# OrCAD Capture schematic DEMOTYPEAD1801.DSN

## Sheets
1 09 PCIA_USER_S: size A3
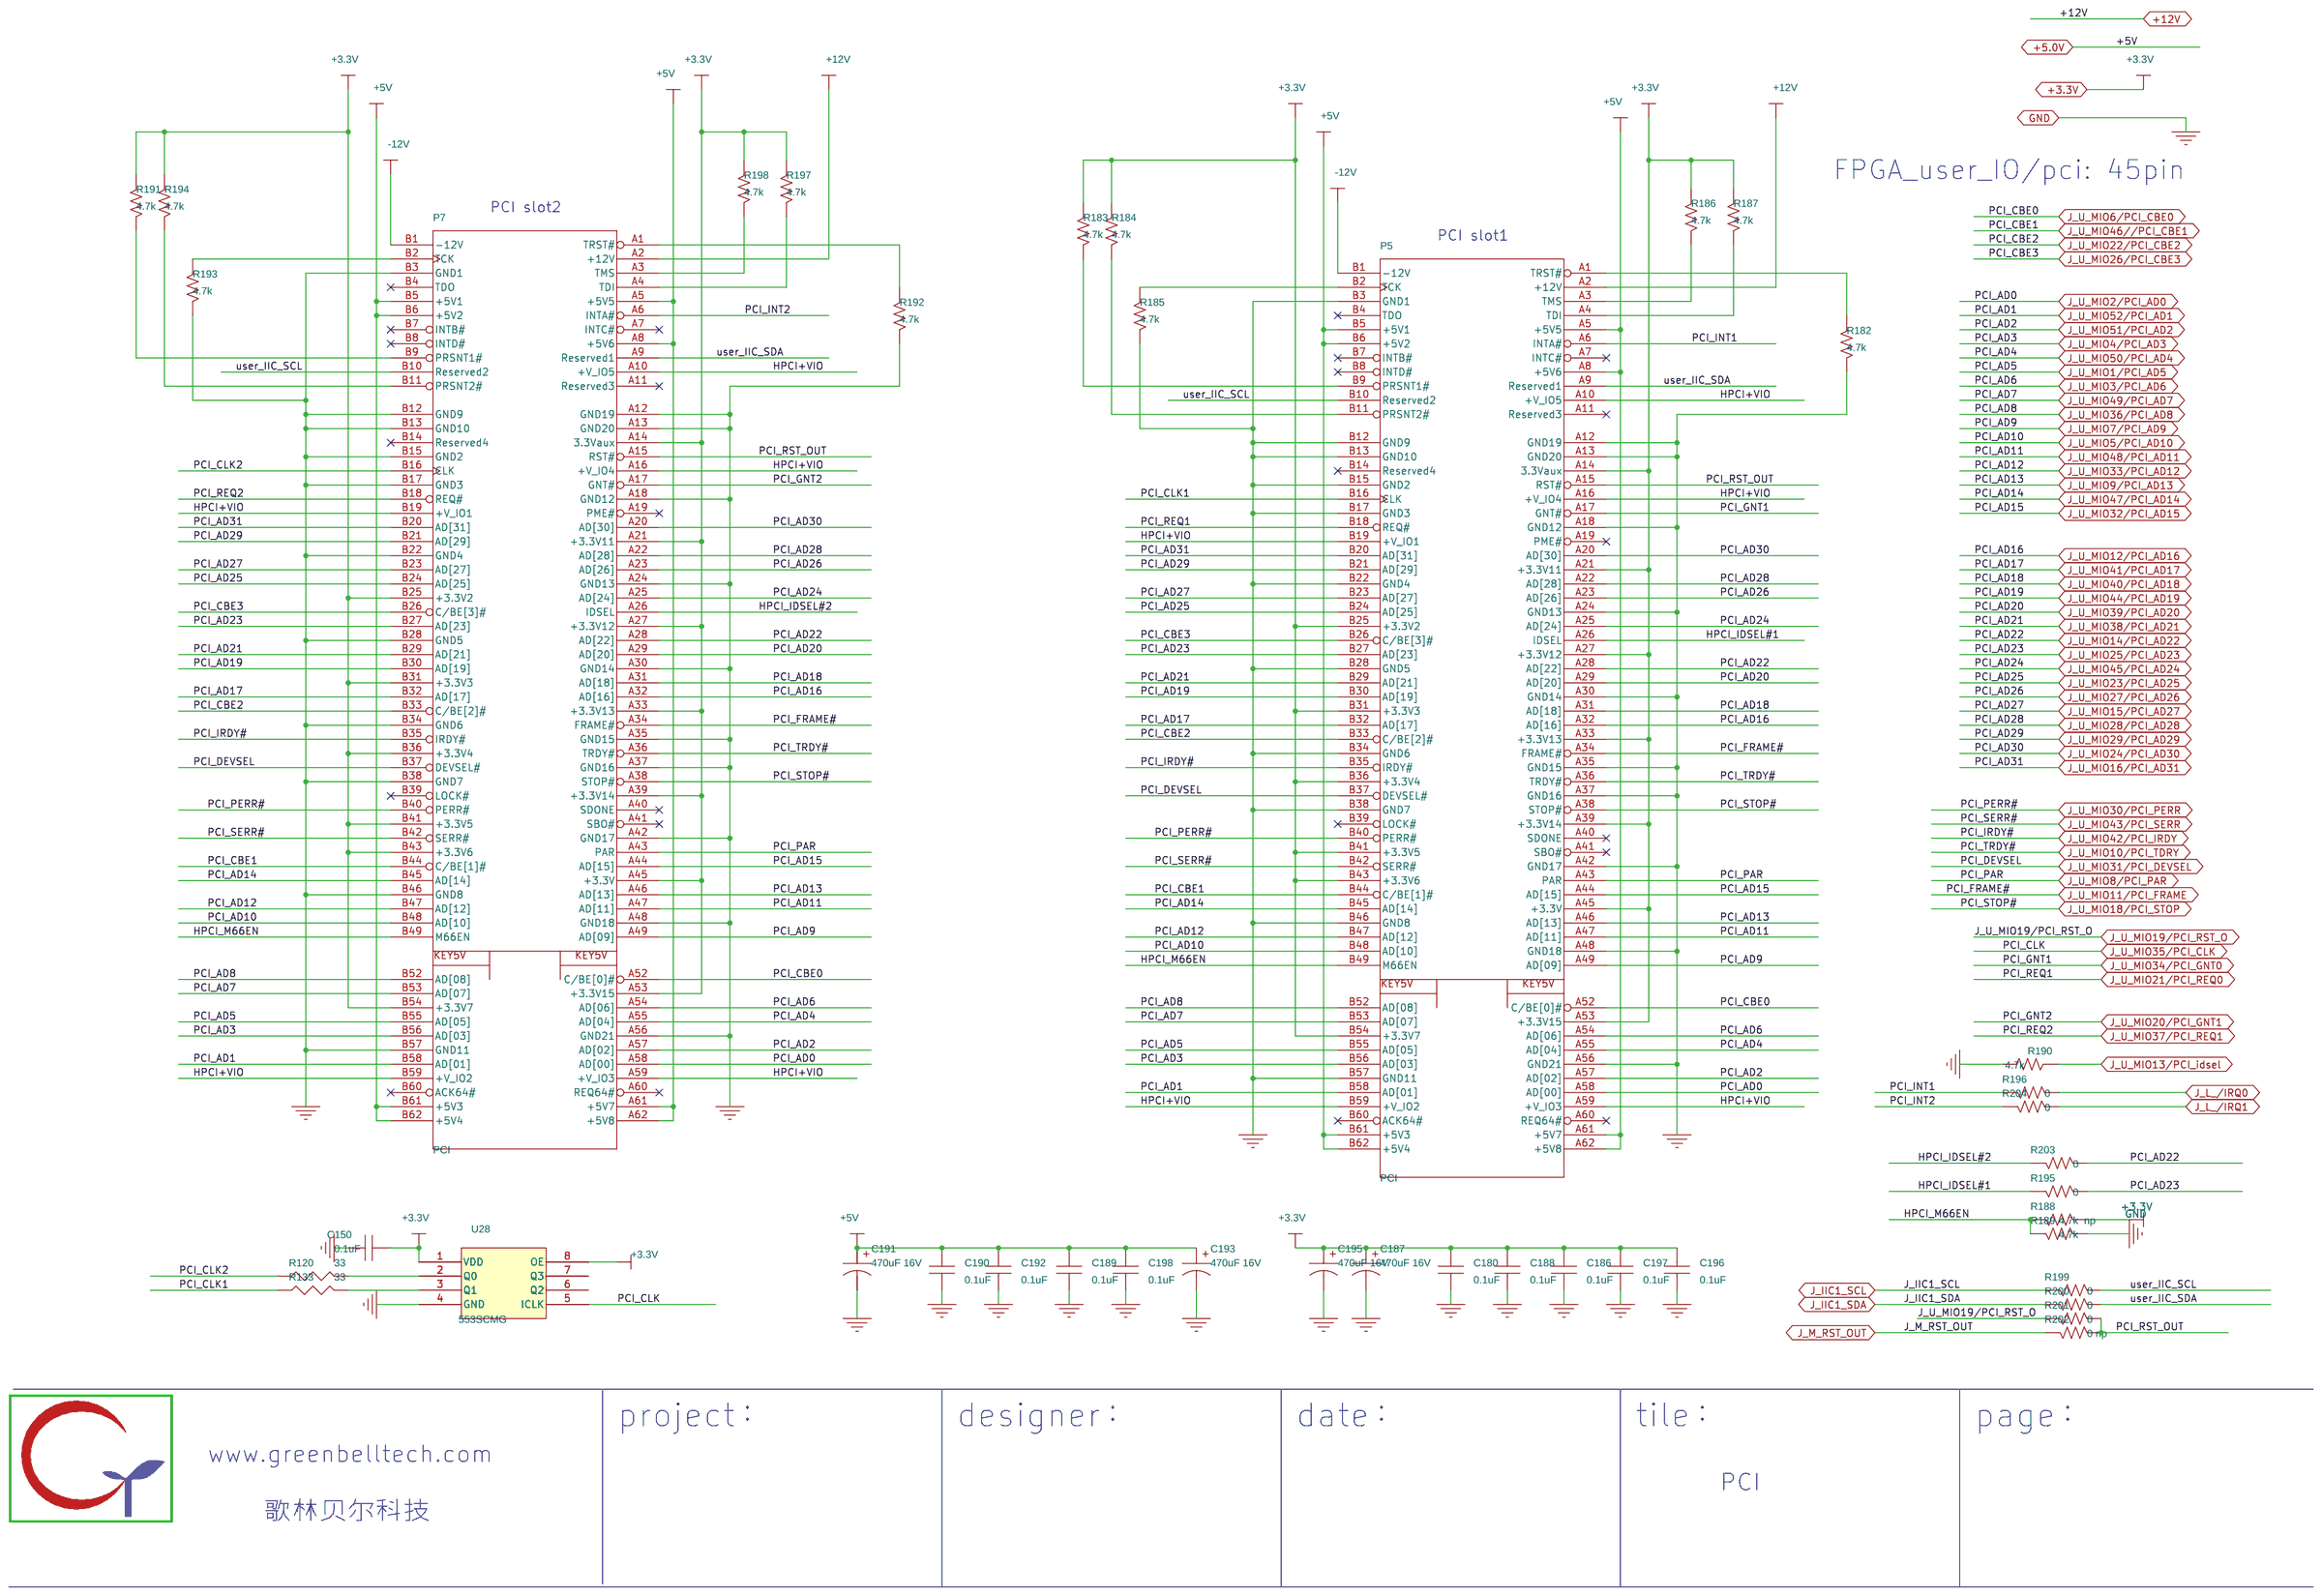
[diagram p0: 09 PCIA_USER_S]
2 00 index
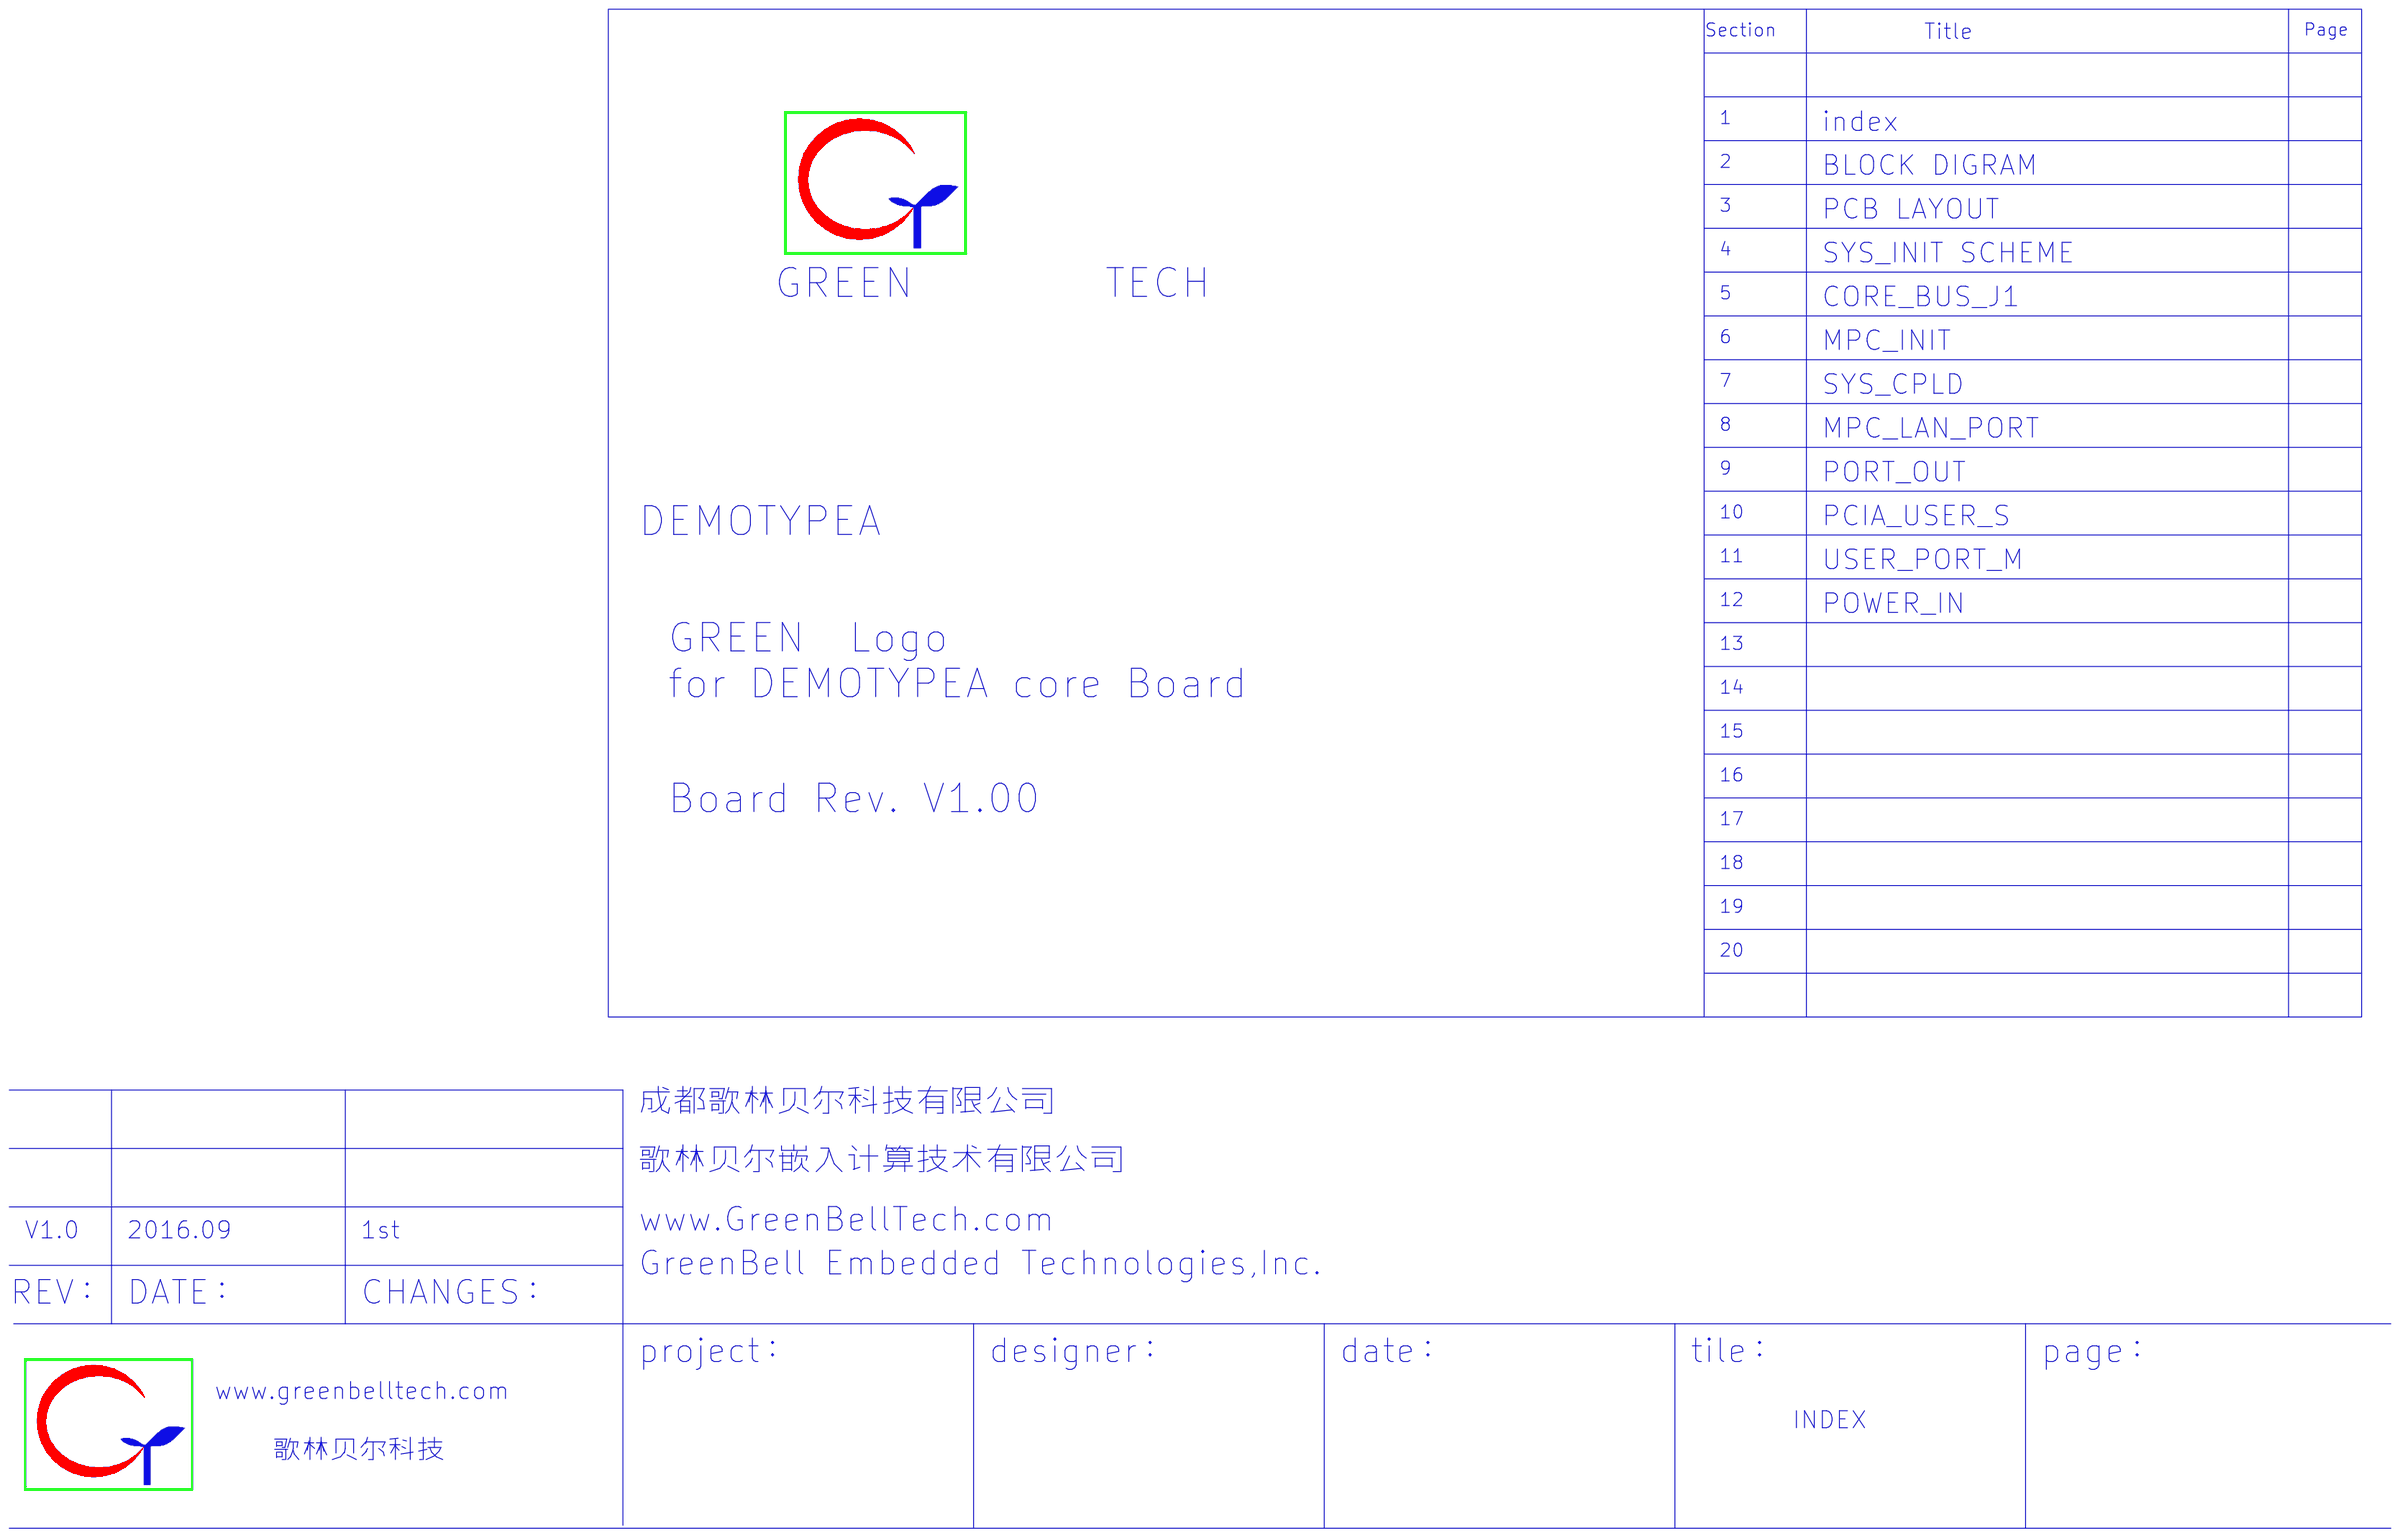
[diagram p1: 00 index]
3 01 BLOCK DIGRAM
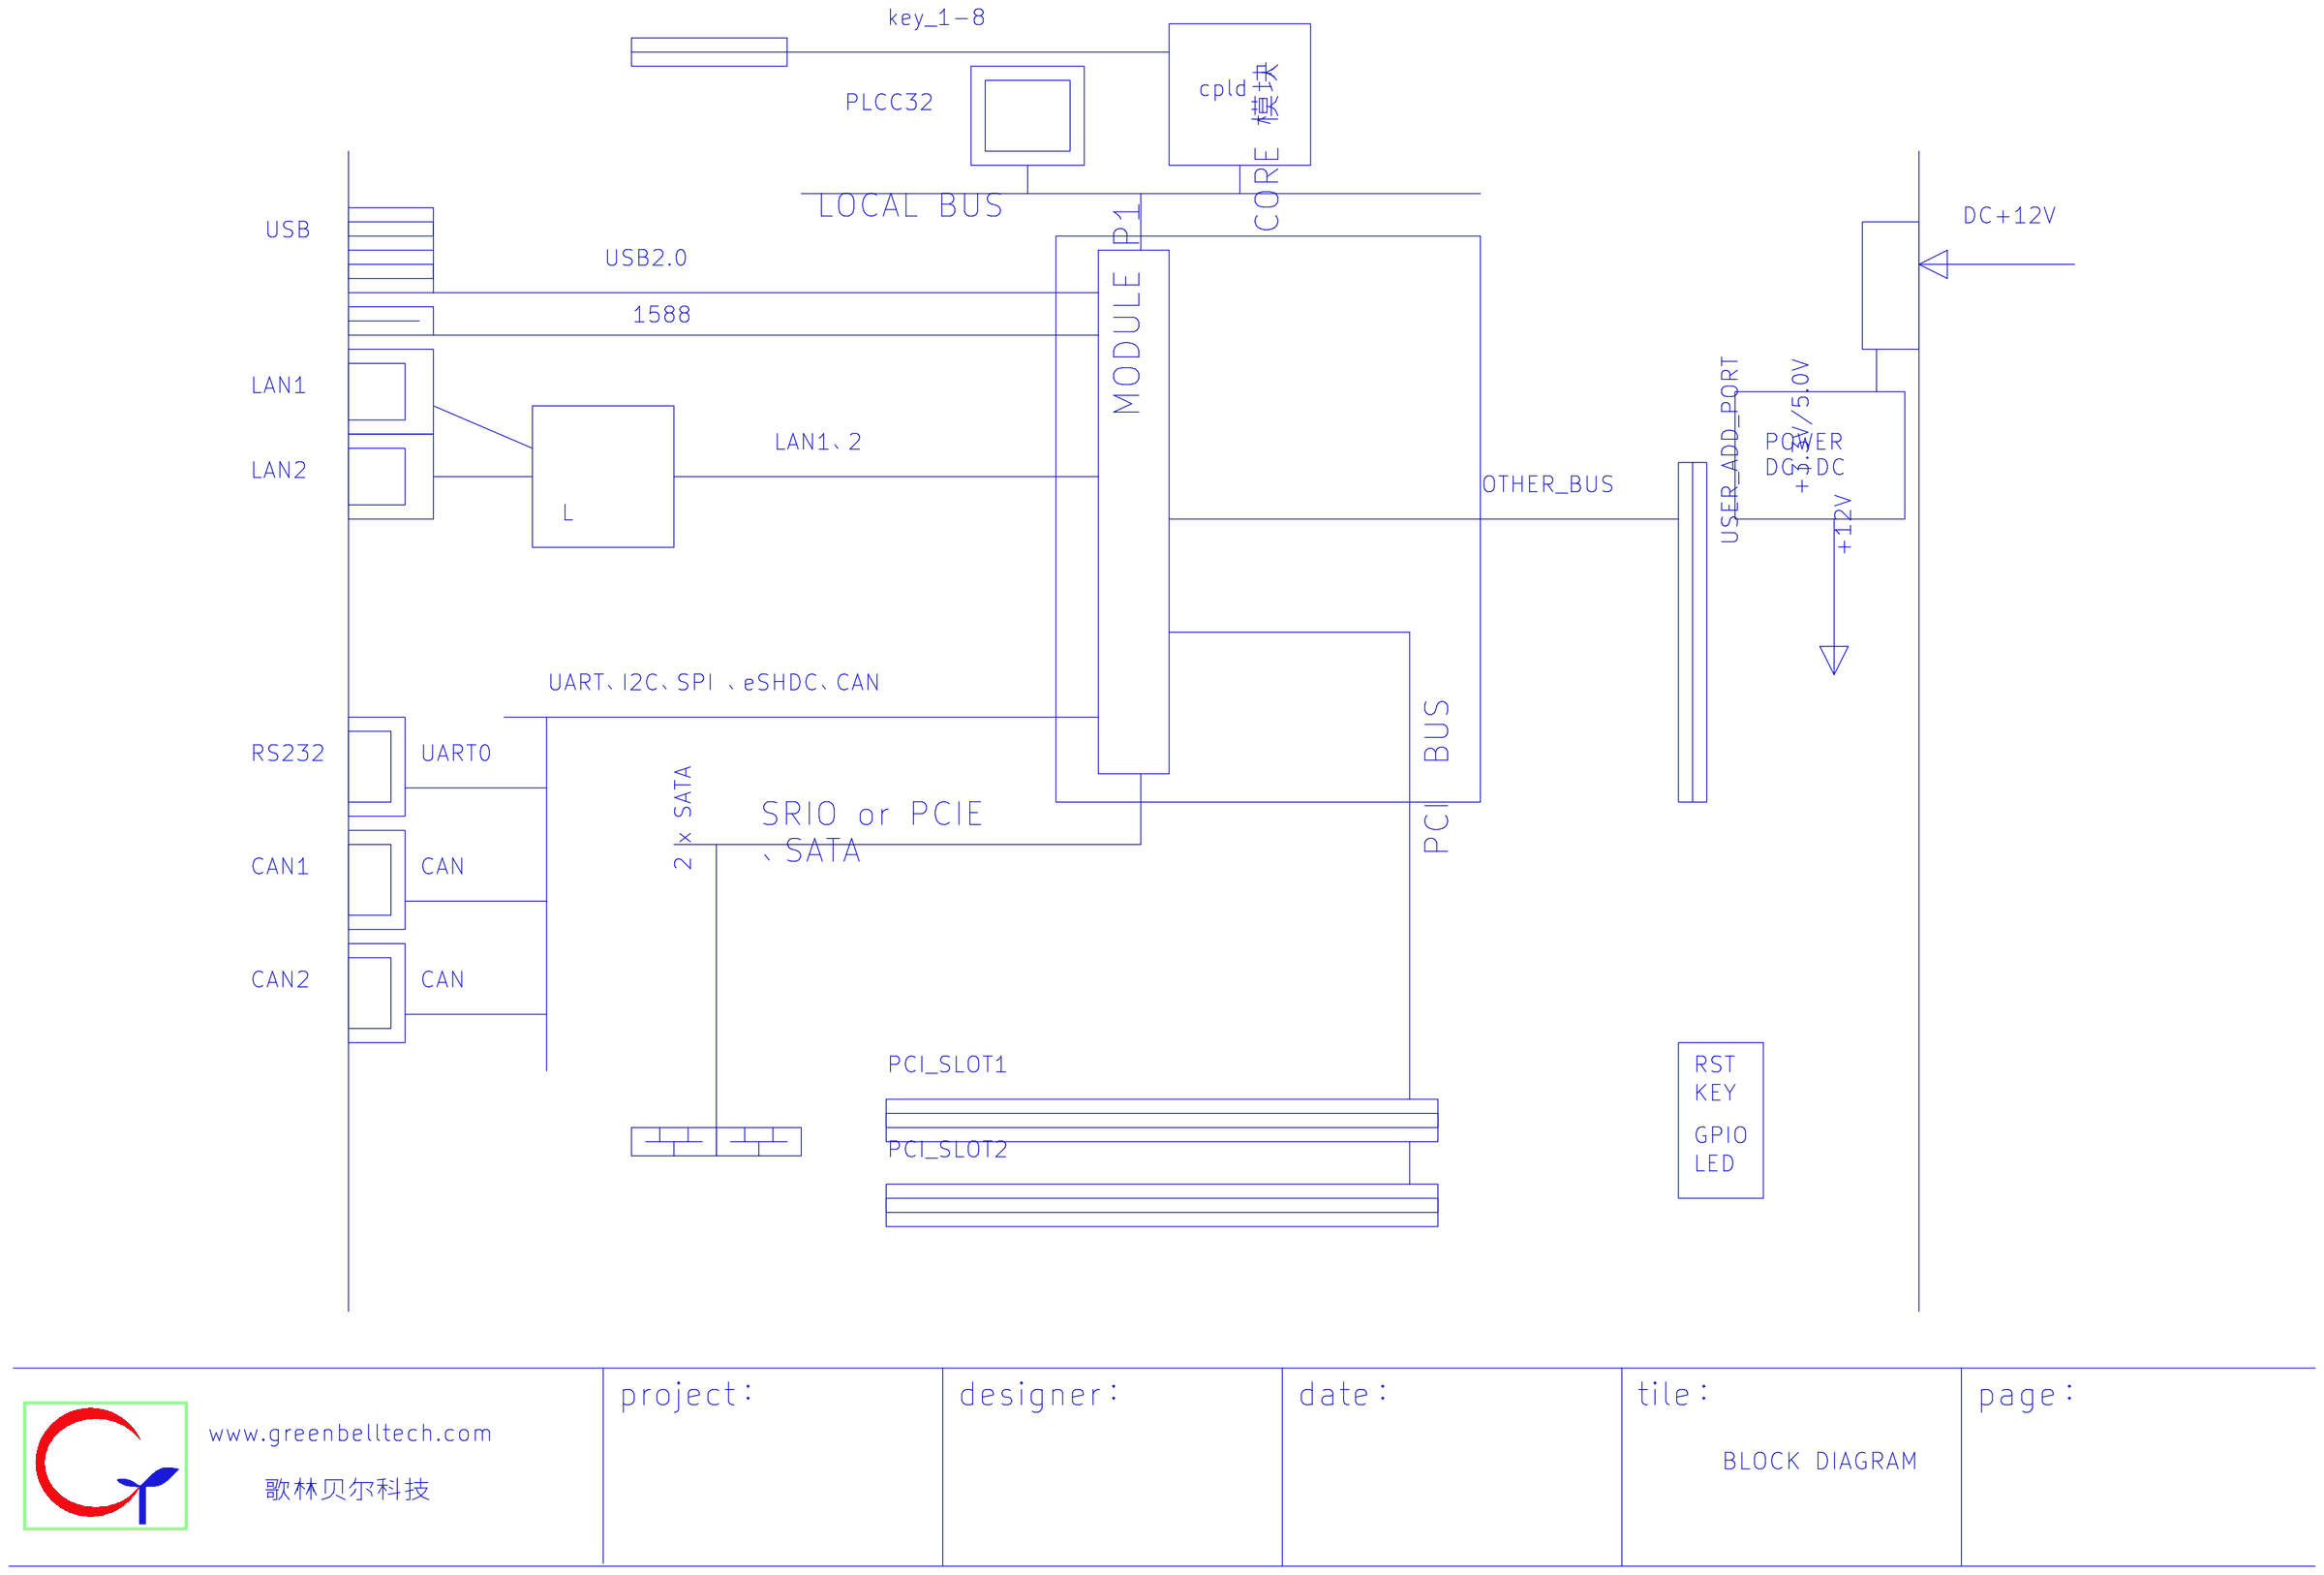
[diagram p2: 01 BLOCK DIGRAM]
4 02 PCB LAYOUT
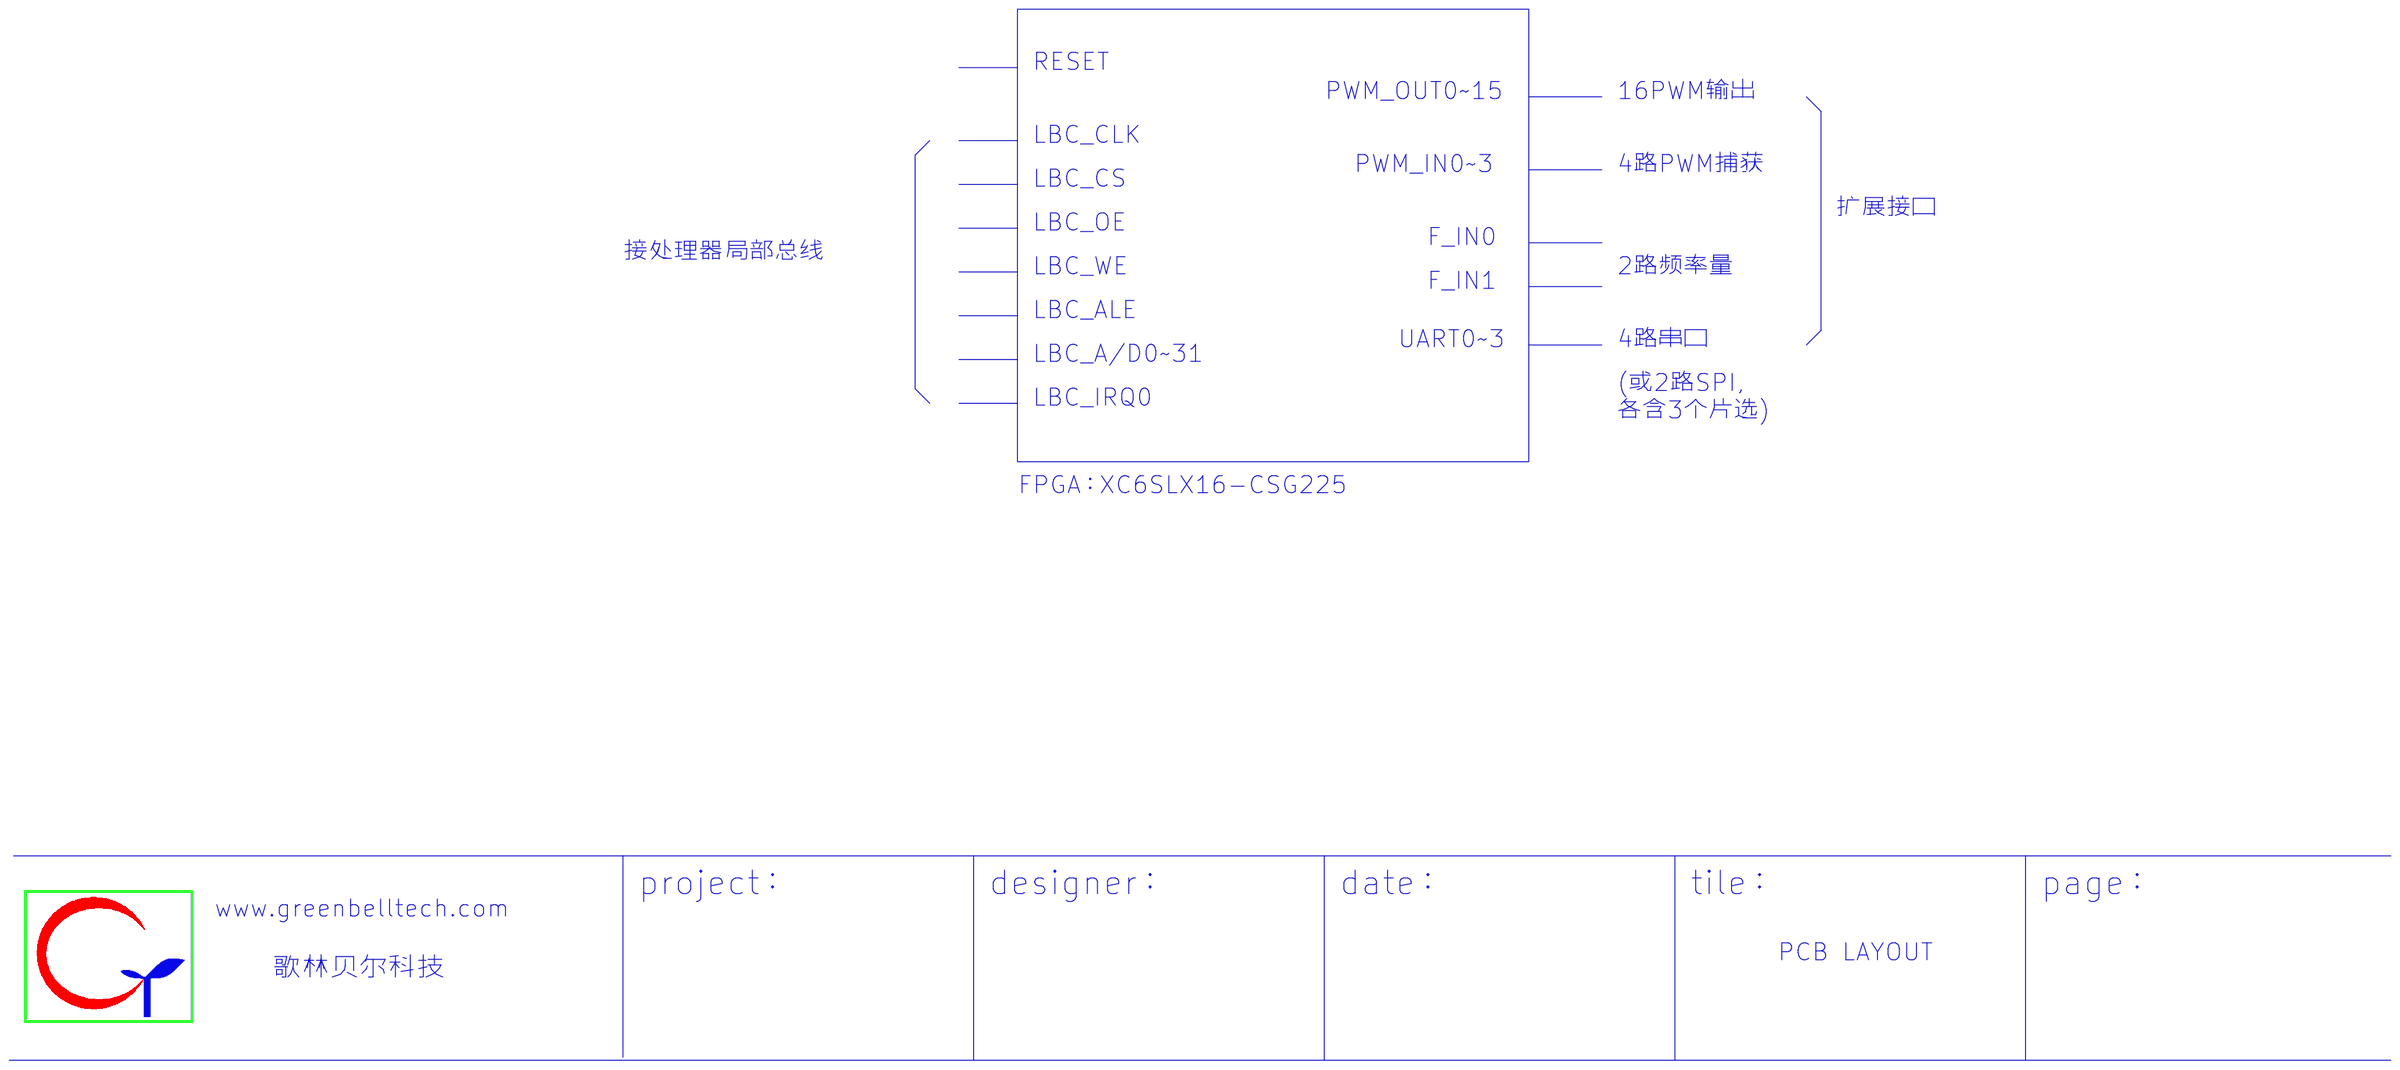
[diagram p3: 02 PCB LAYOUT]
5 03 SYS_INIT SCHEME
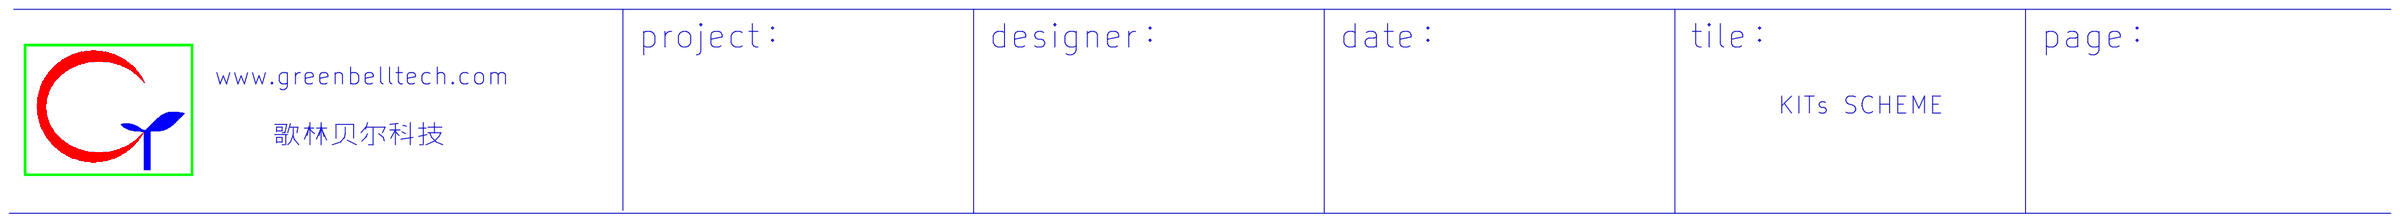
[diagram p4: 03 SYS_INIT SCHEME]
6 05 SYS_INIT: size A3
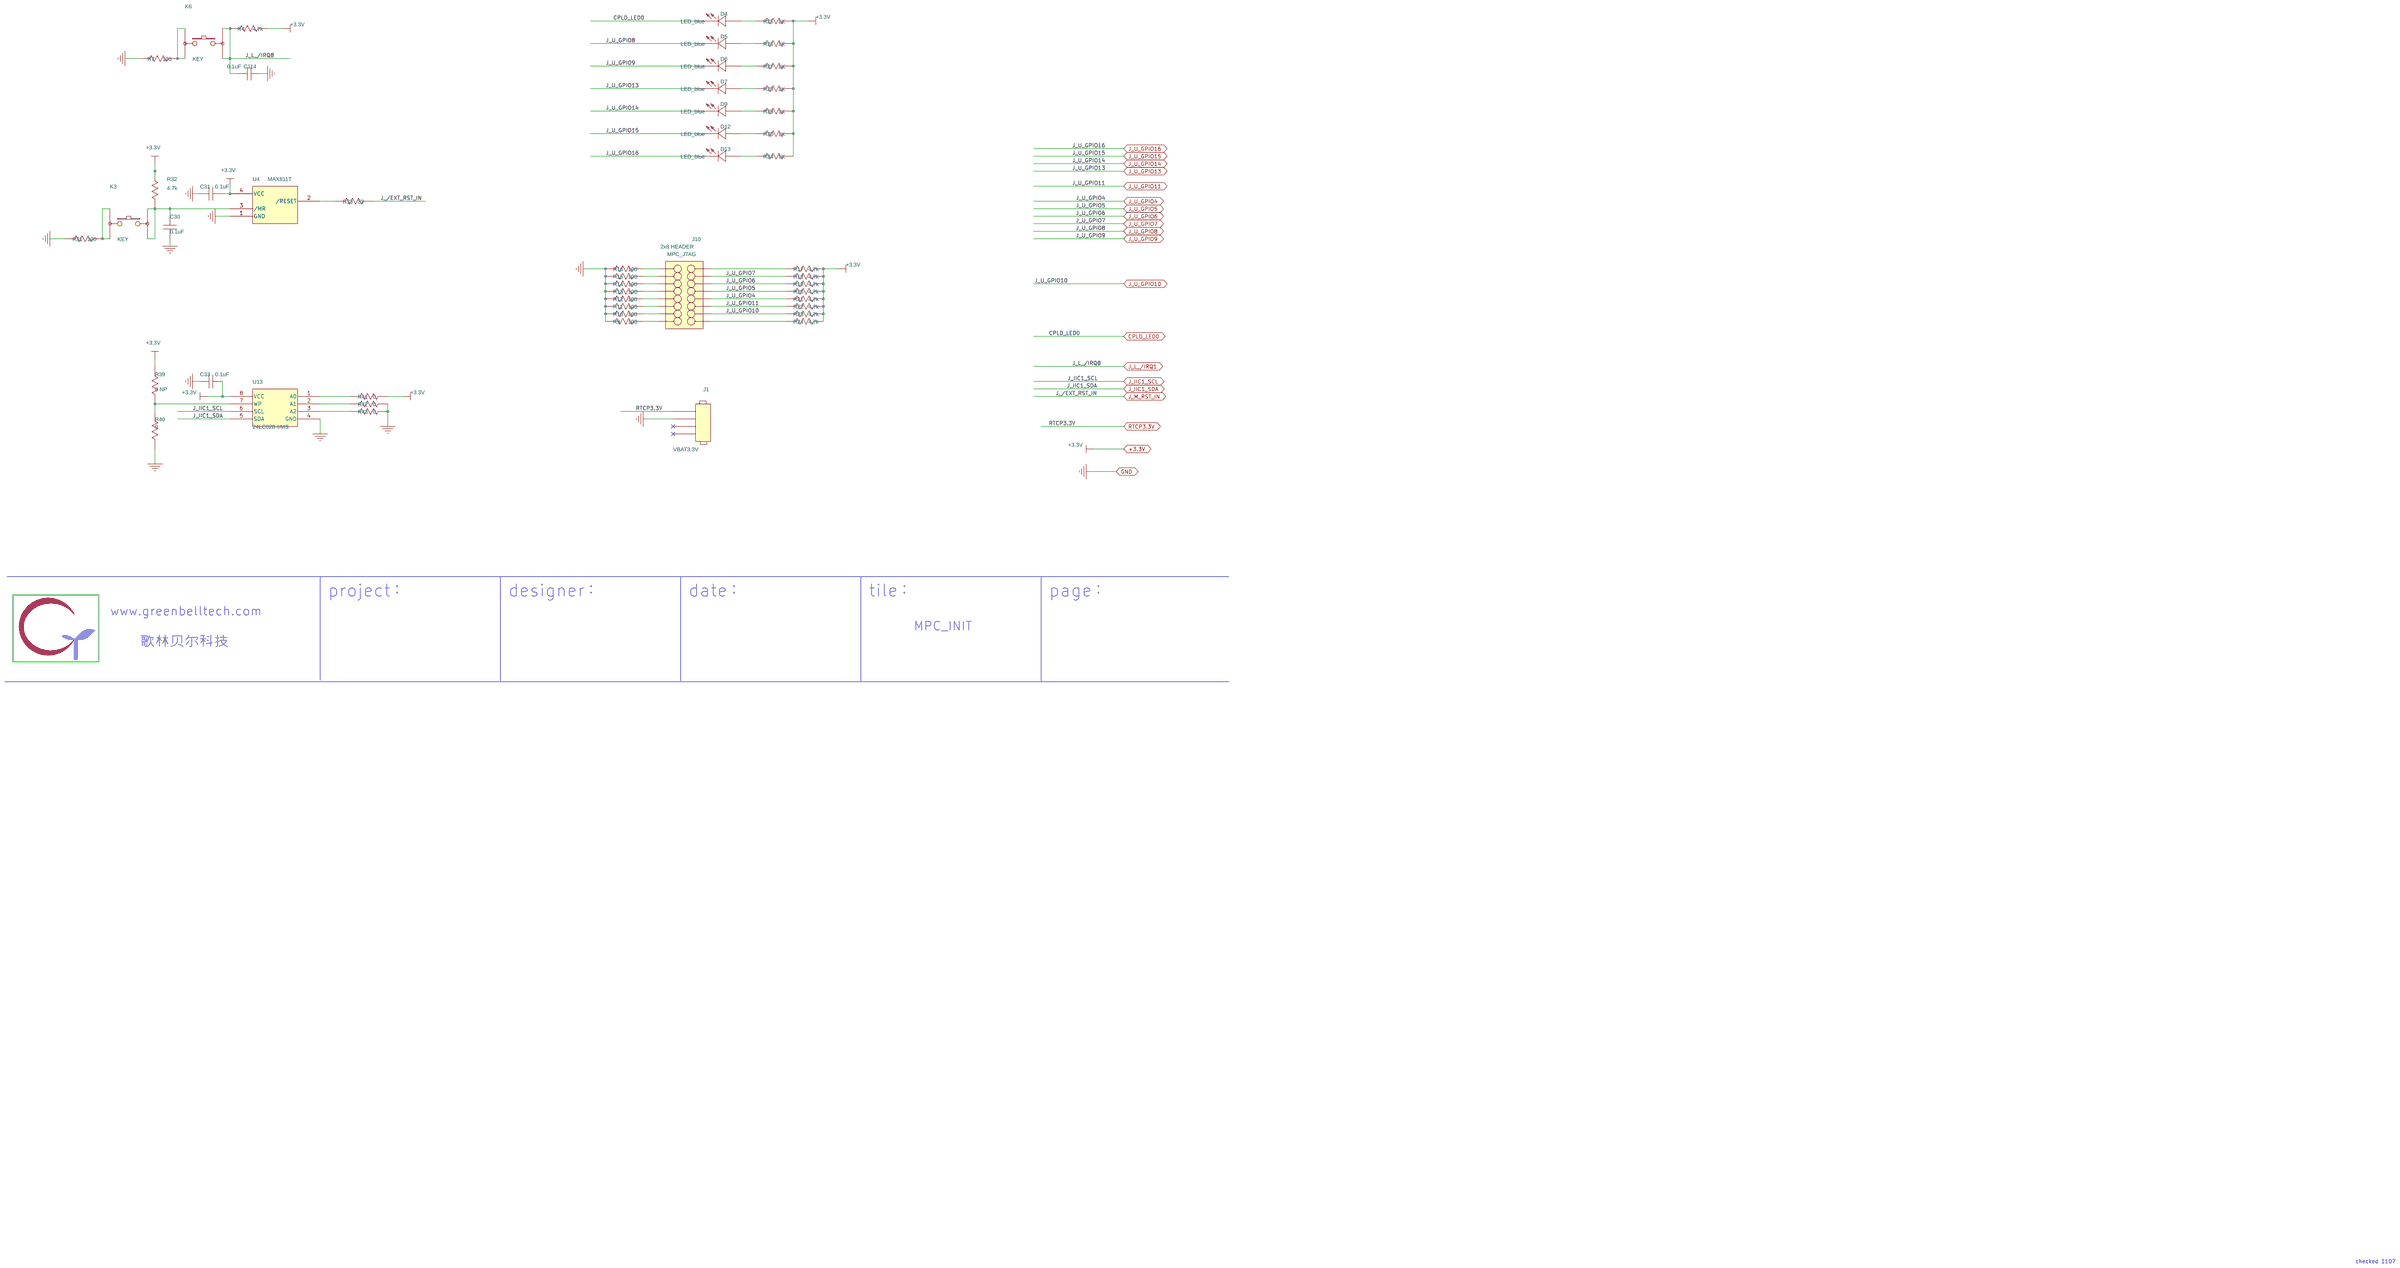
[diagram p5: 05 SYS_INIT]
7 06 SYS_CPLD: size A3
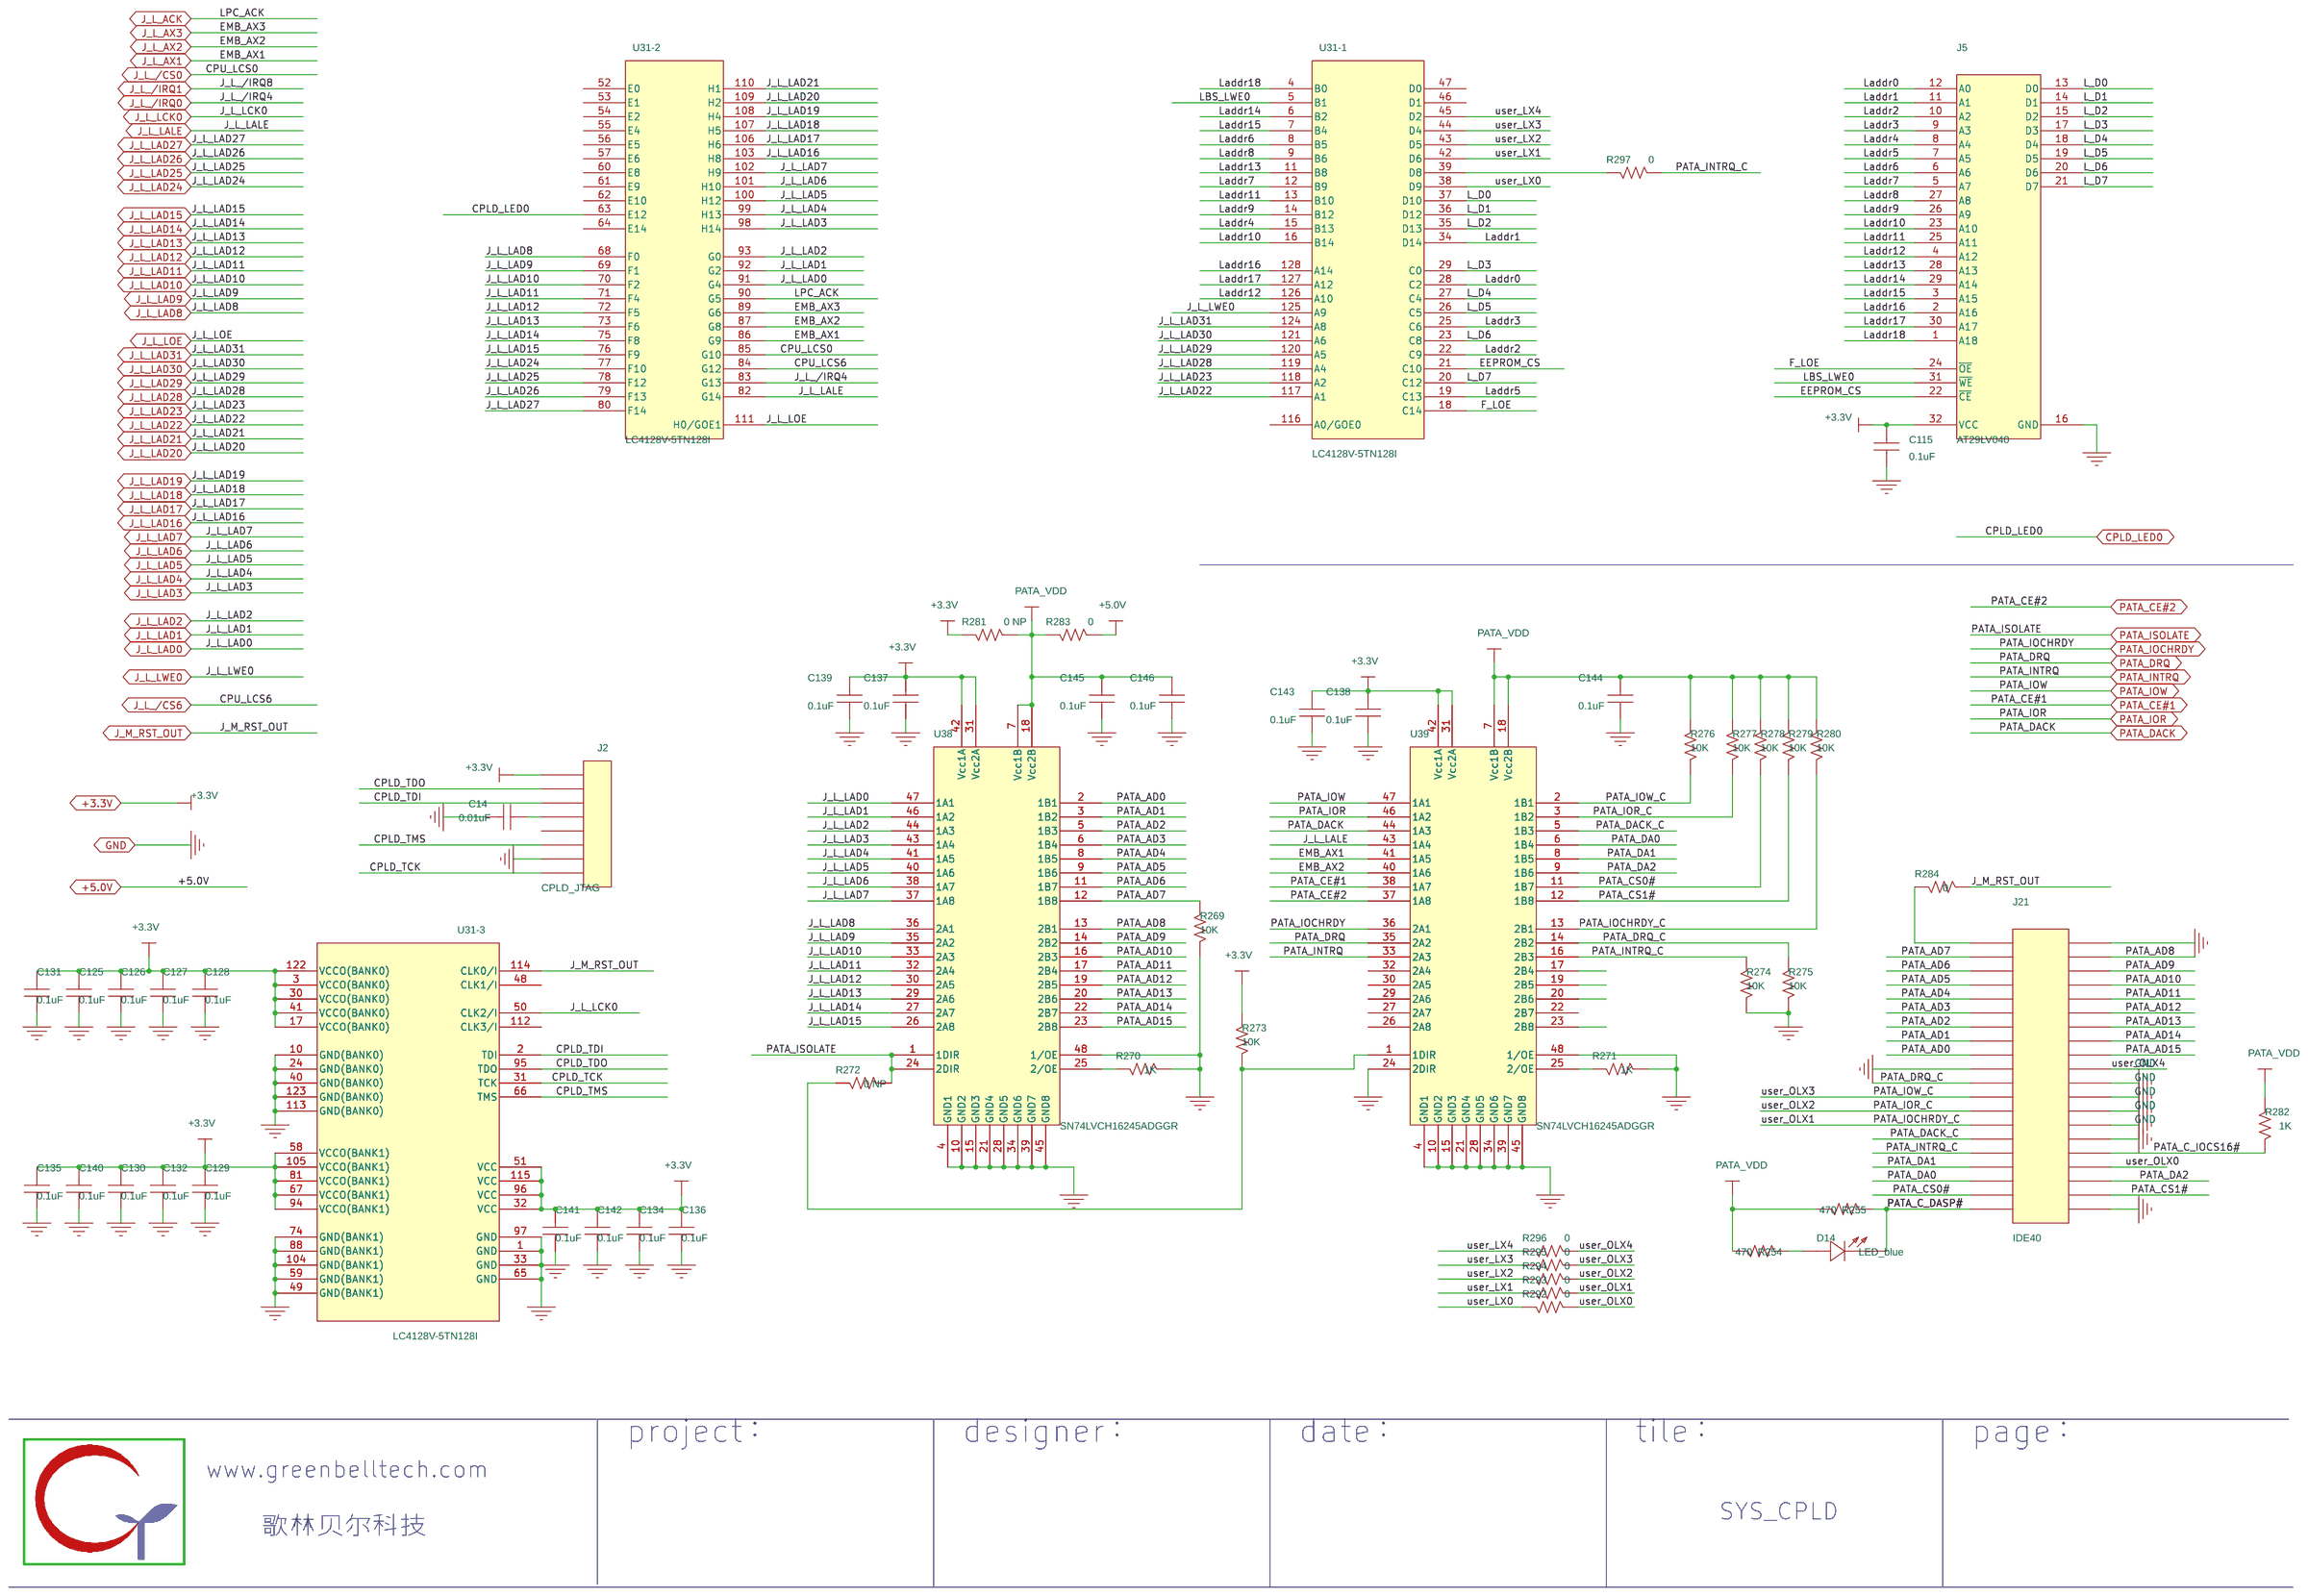
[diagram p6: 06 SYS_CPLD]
8 10 USER_PORT_M: size A3
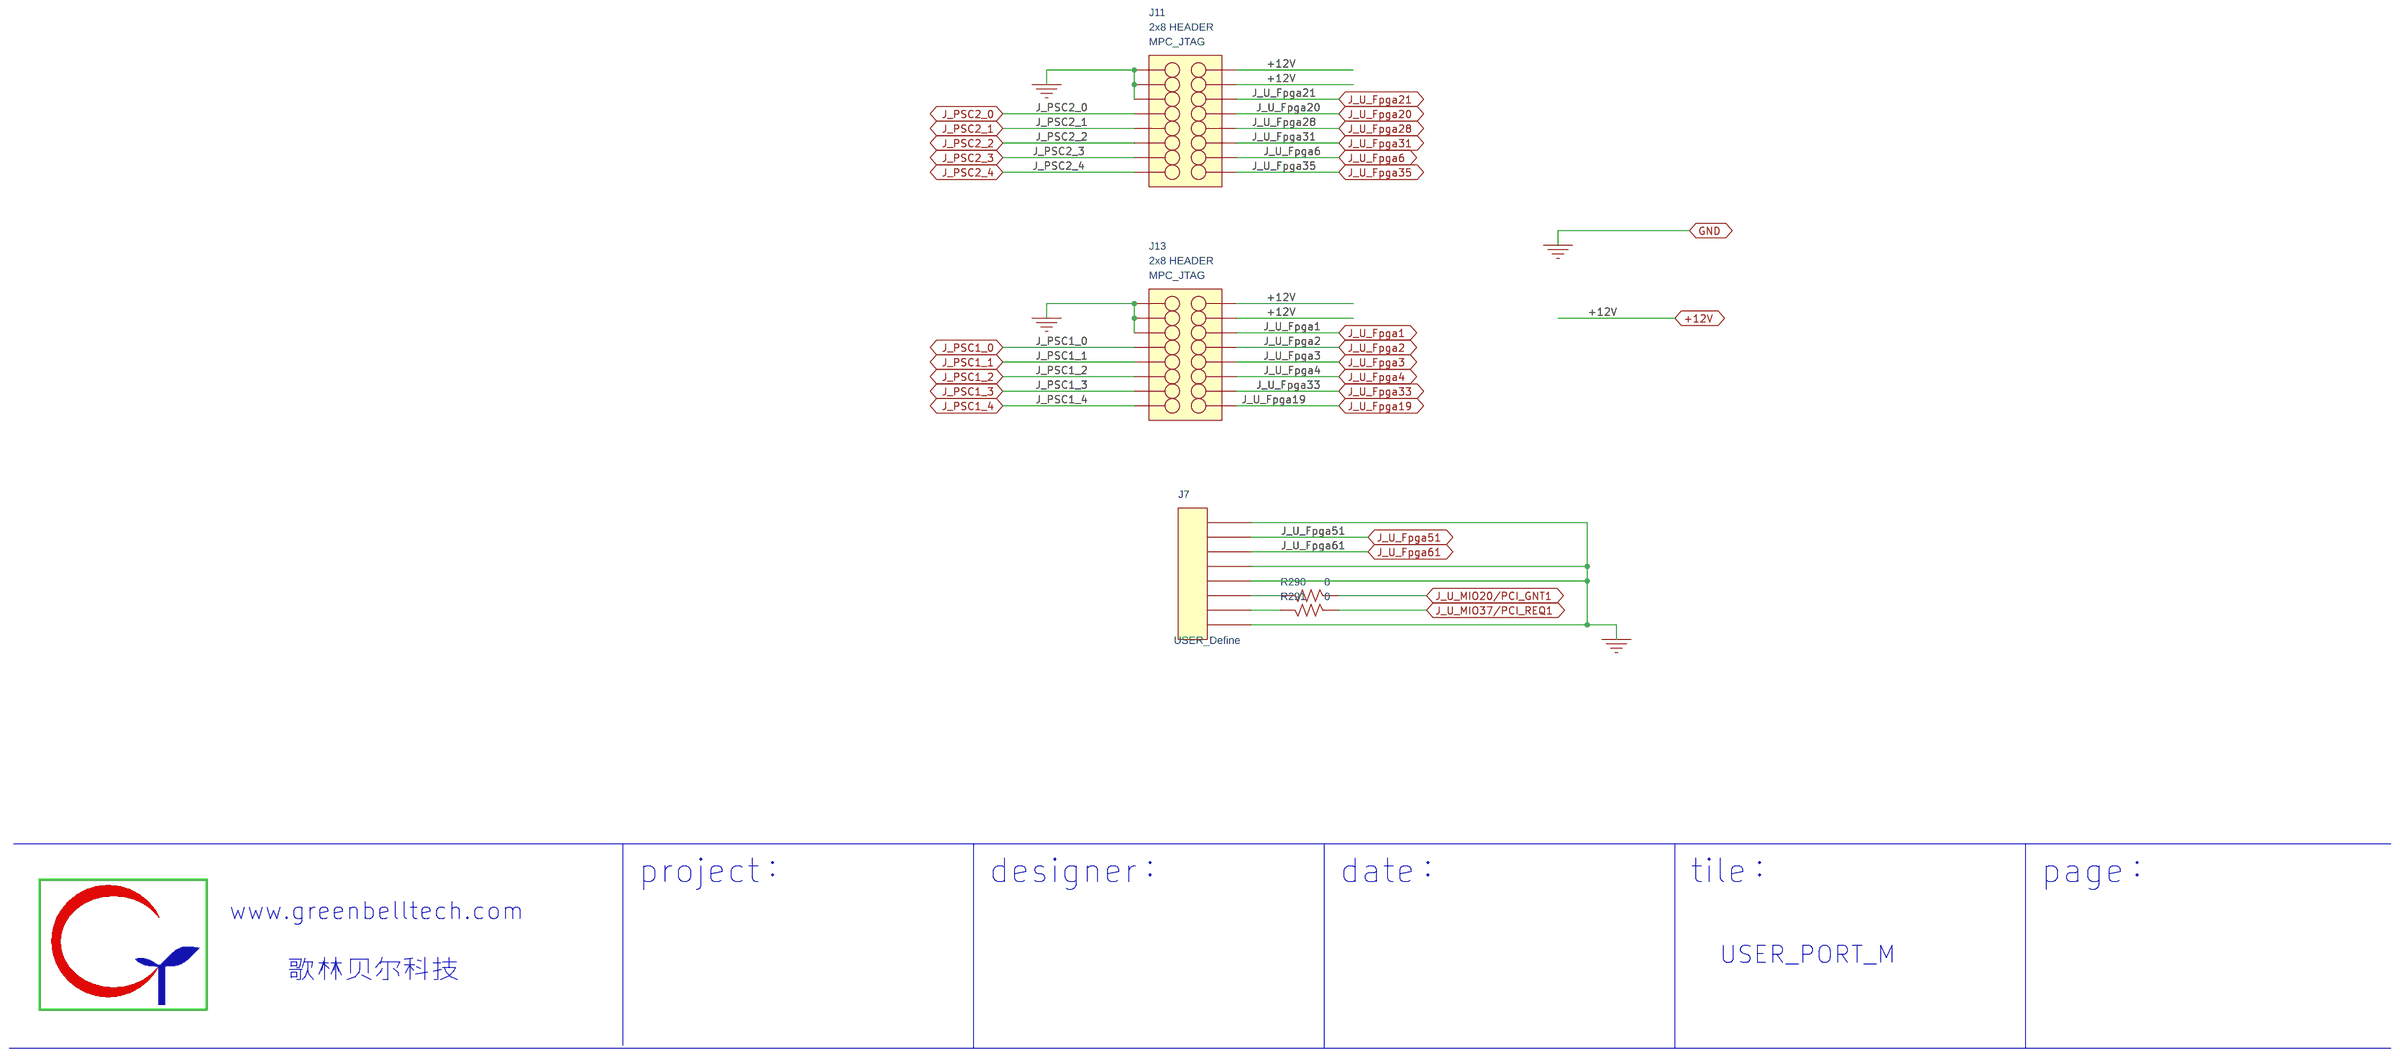
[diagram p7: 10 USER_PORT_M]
9 07 MPC_LAN_PORT: size A3
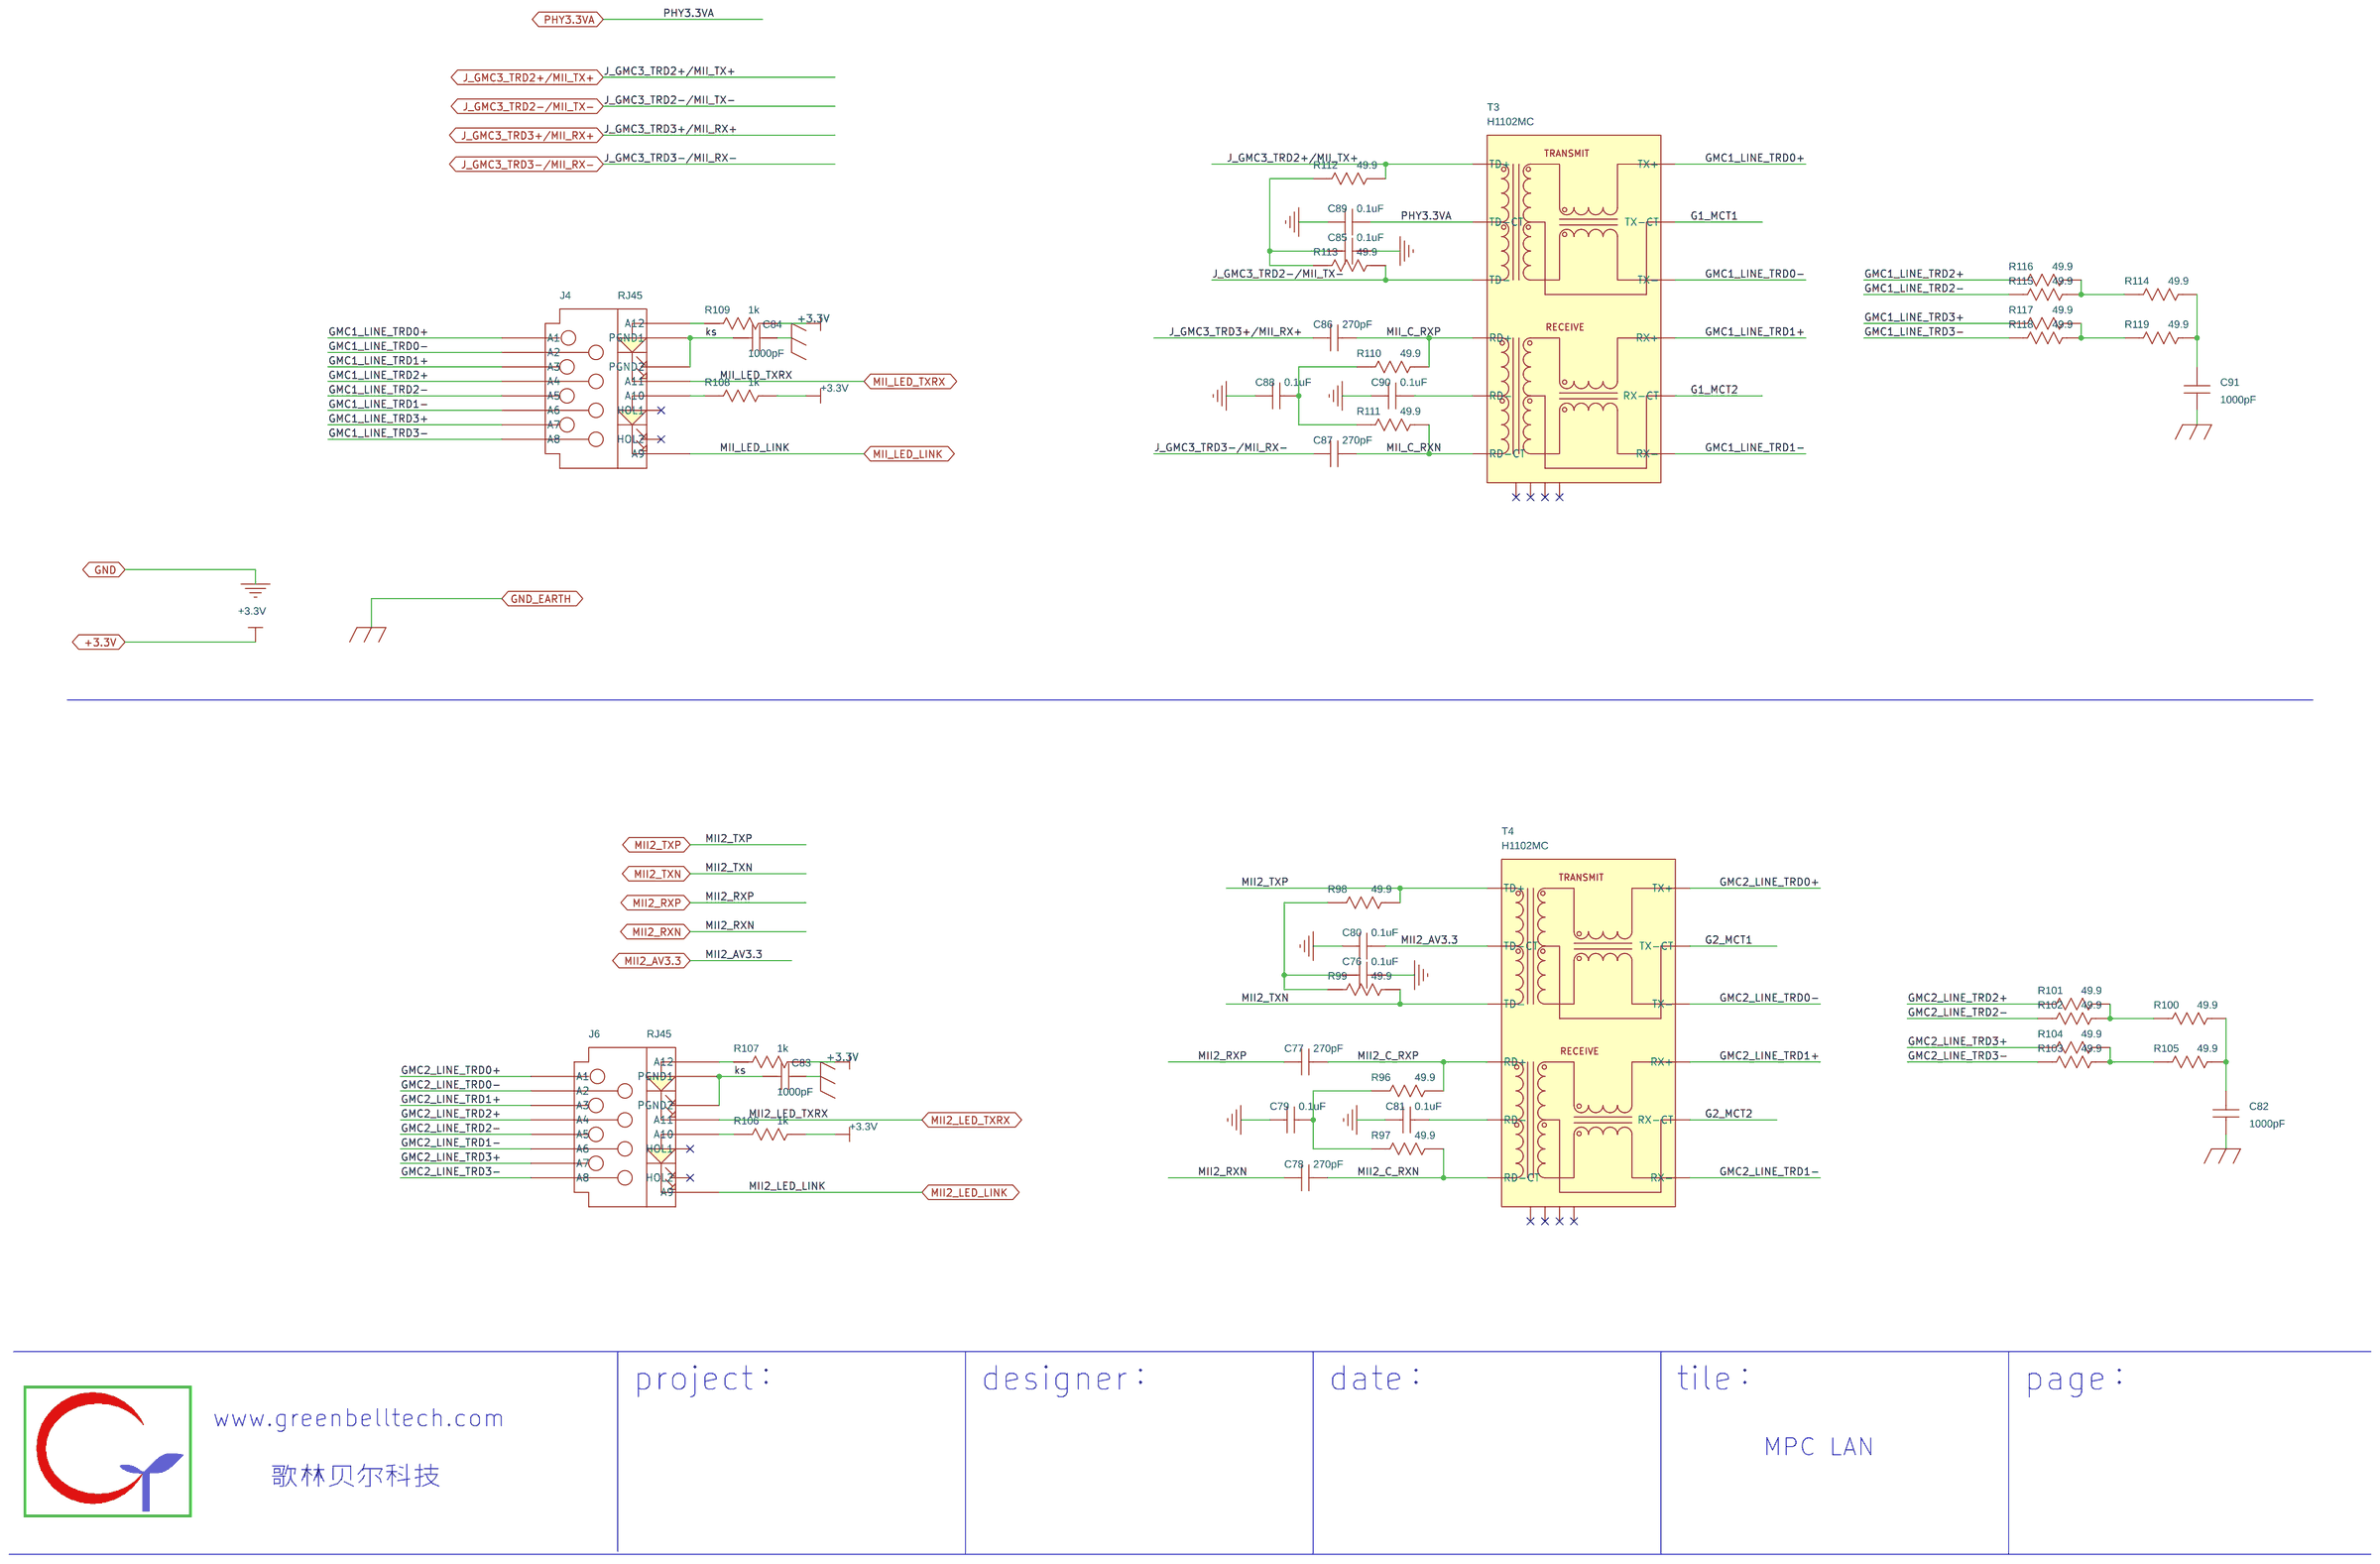
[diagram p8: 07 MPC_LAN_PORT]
10 08 PORT_OUT: size A3
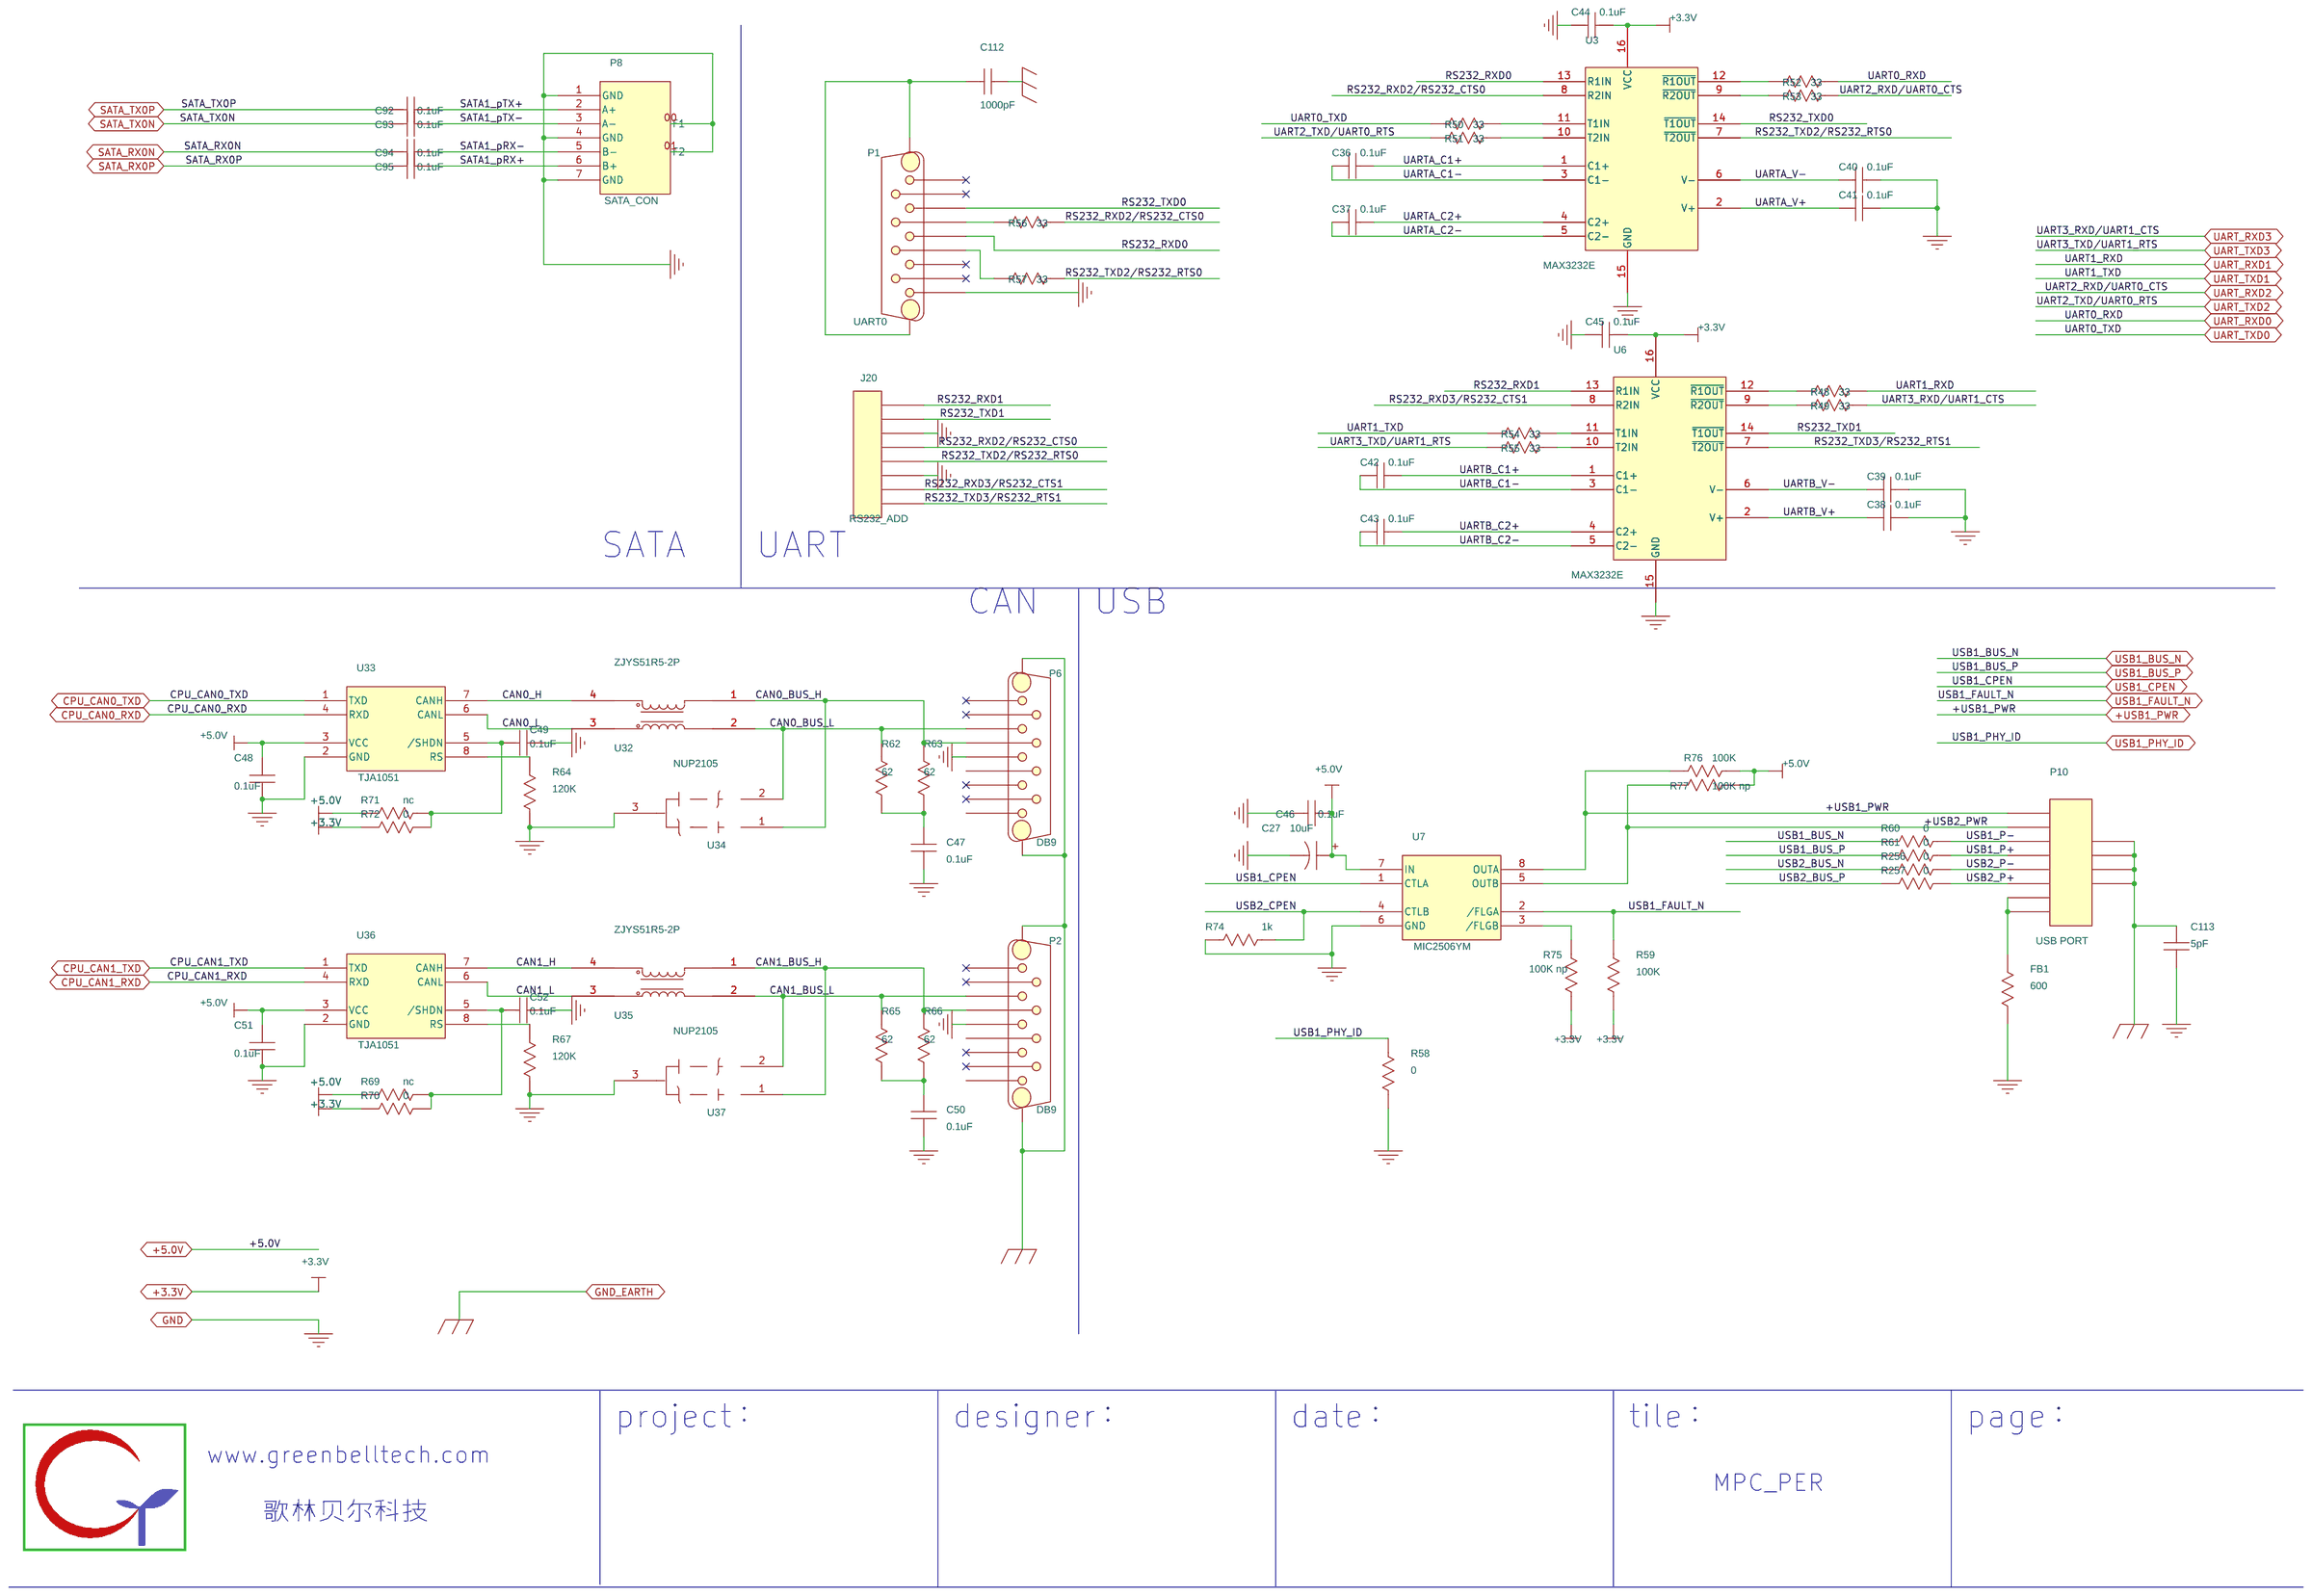
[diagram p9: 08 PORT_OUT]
11 11 POWER_IN   CCC: size A3
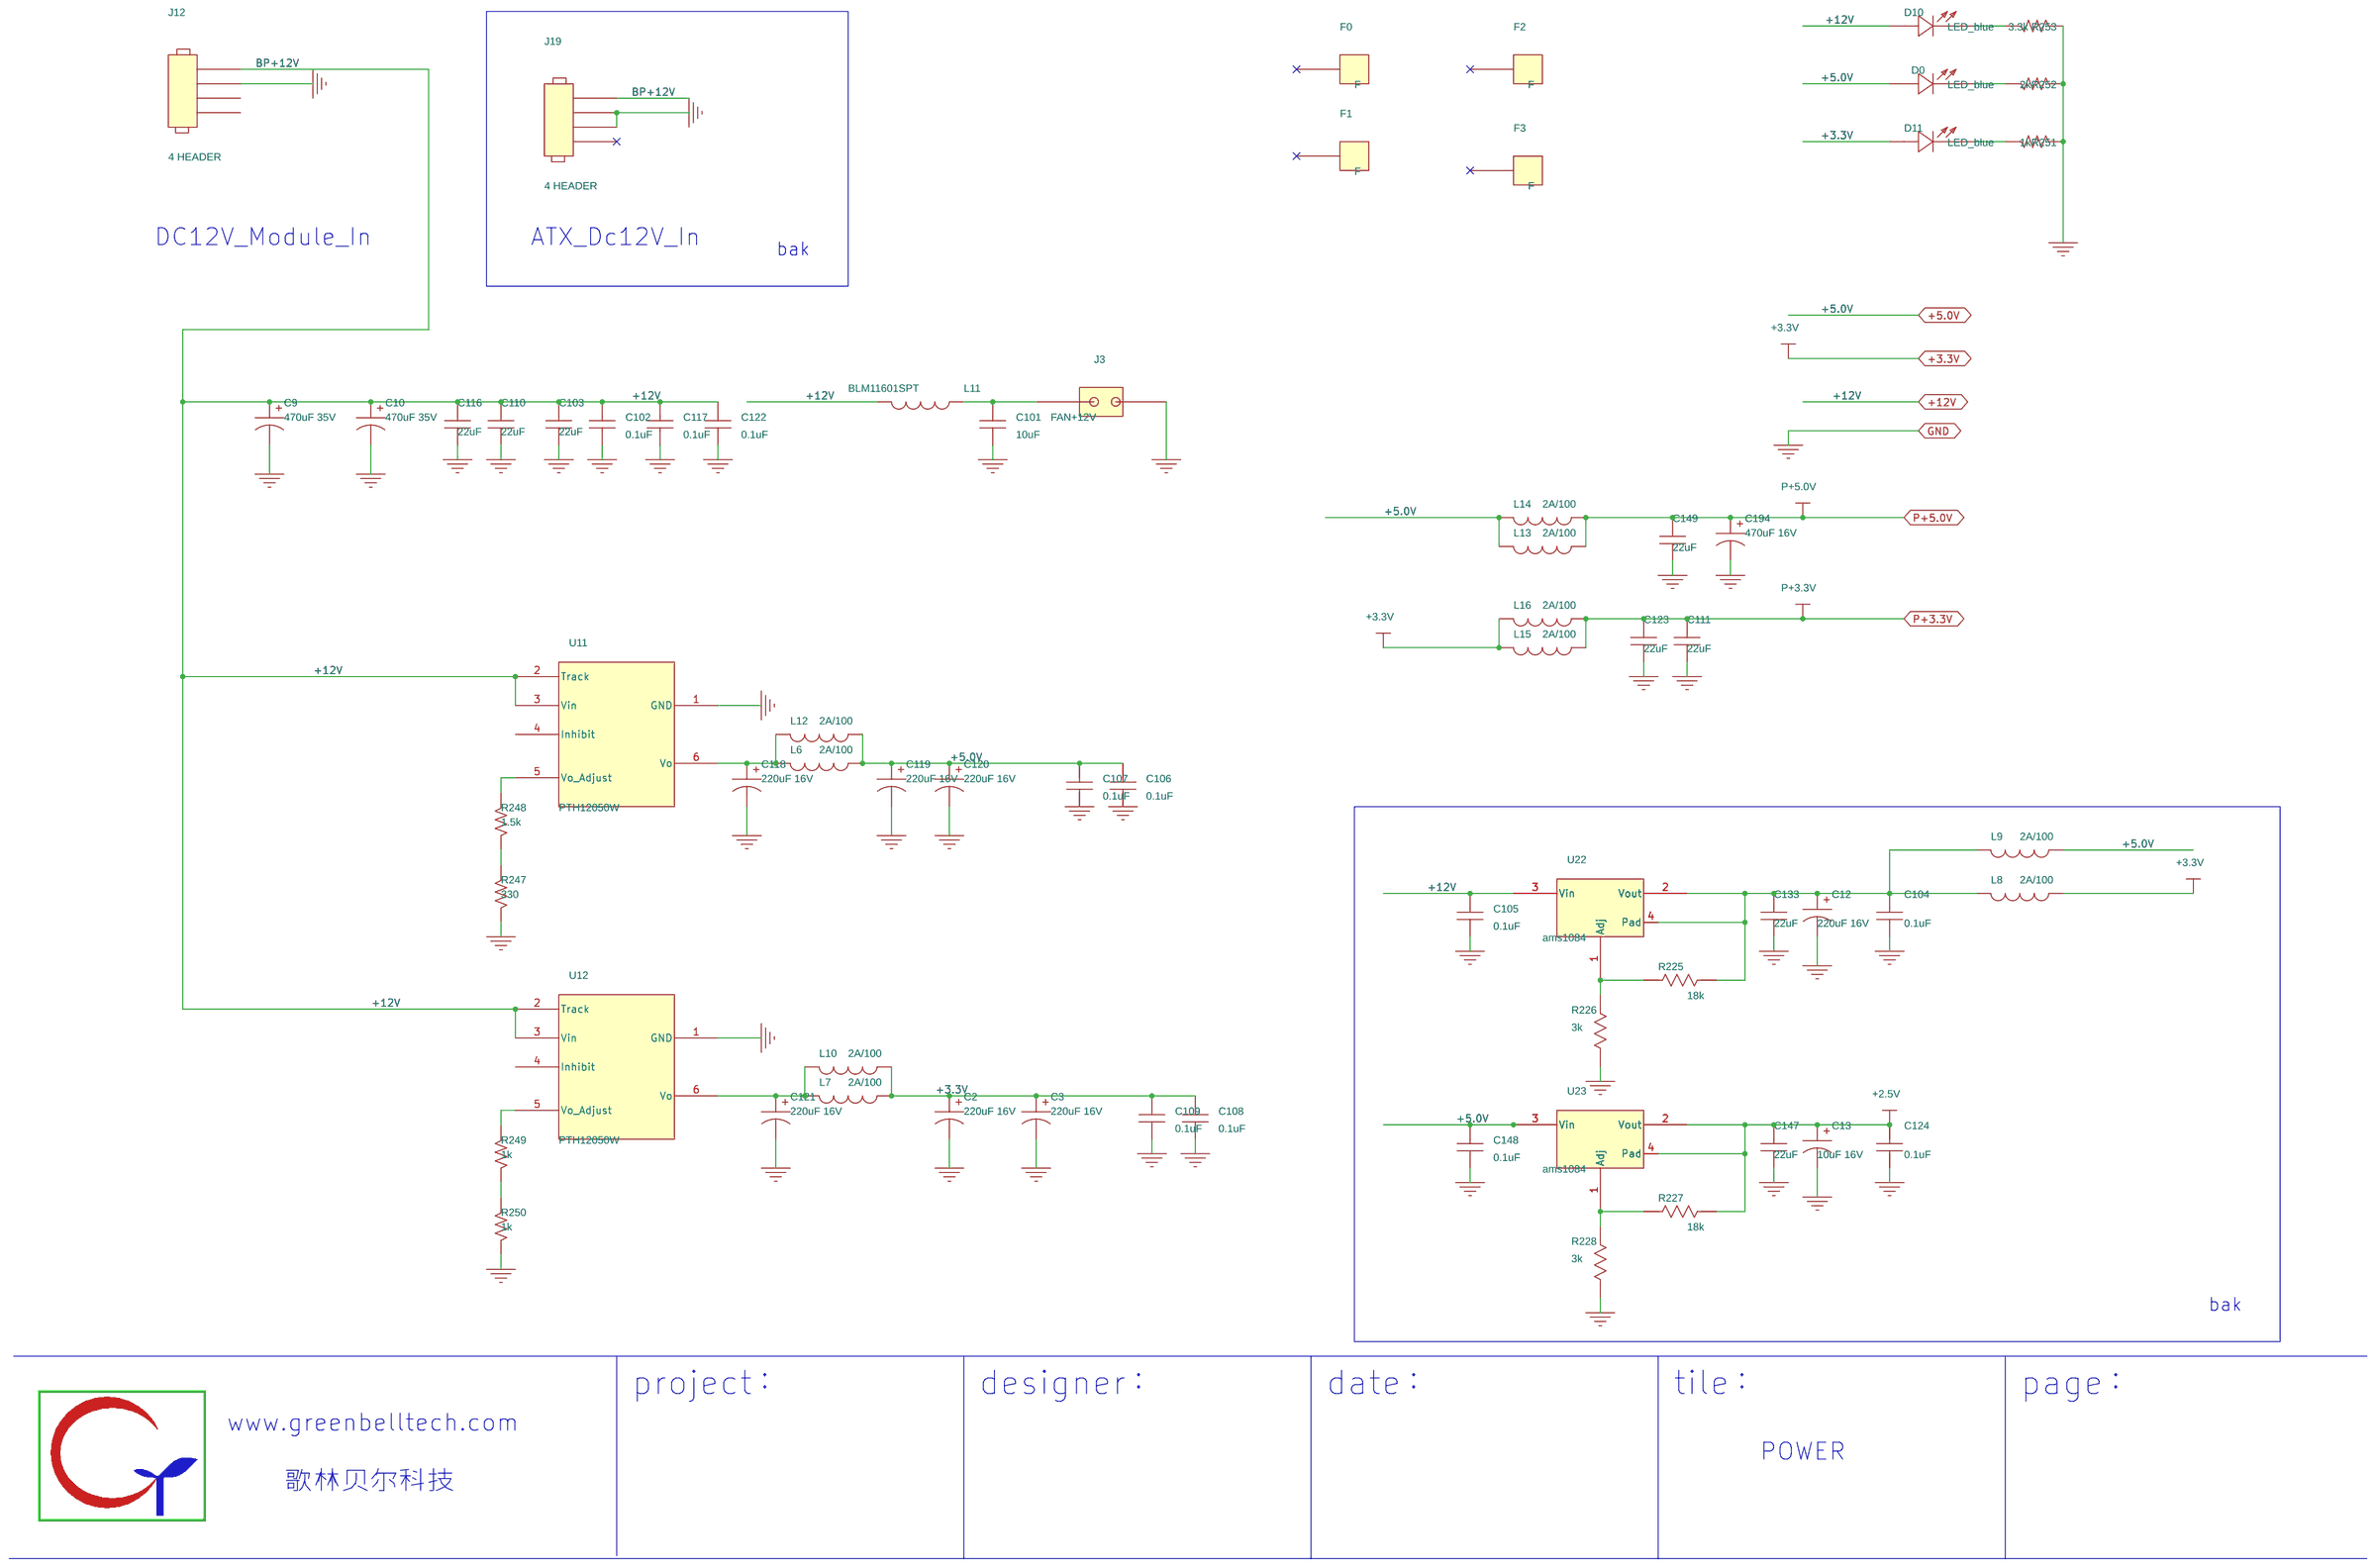
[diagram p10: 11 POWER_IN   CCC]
12 04 CORE_BUS_J1: size A3
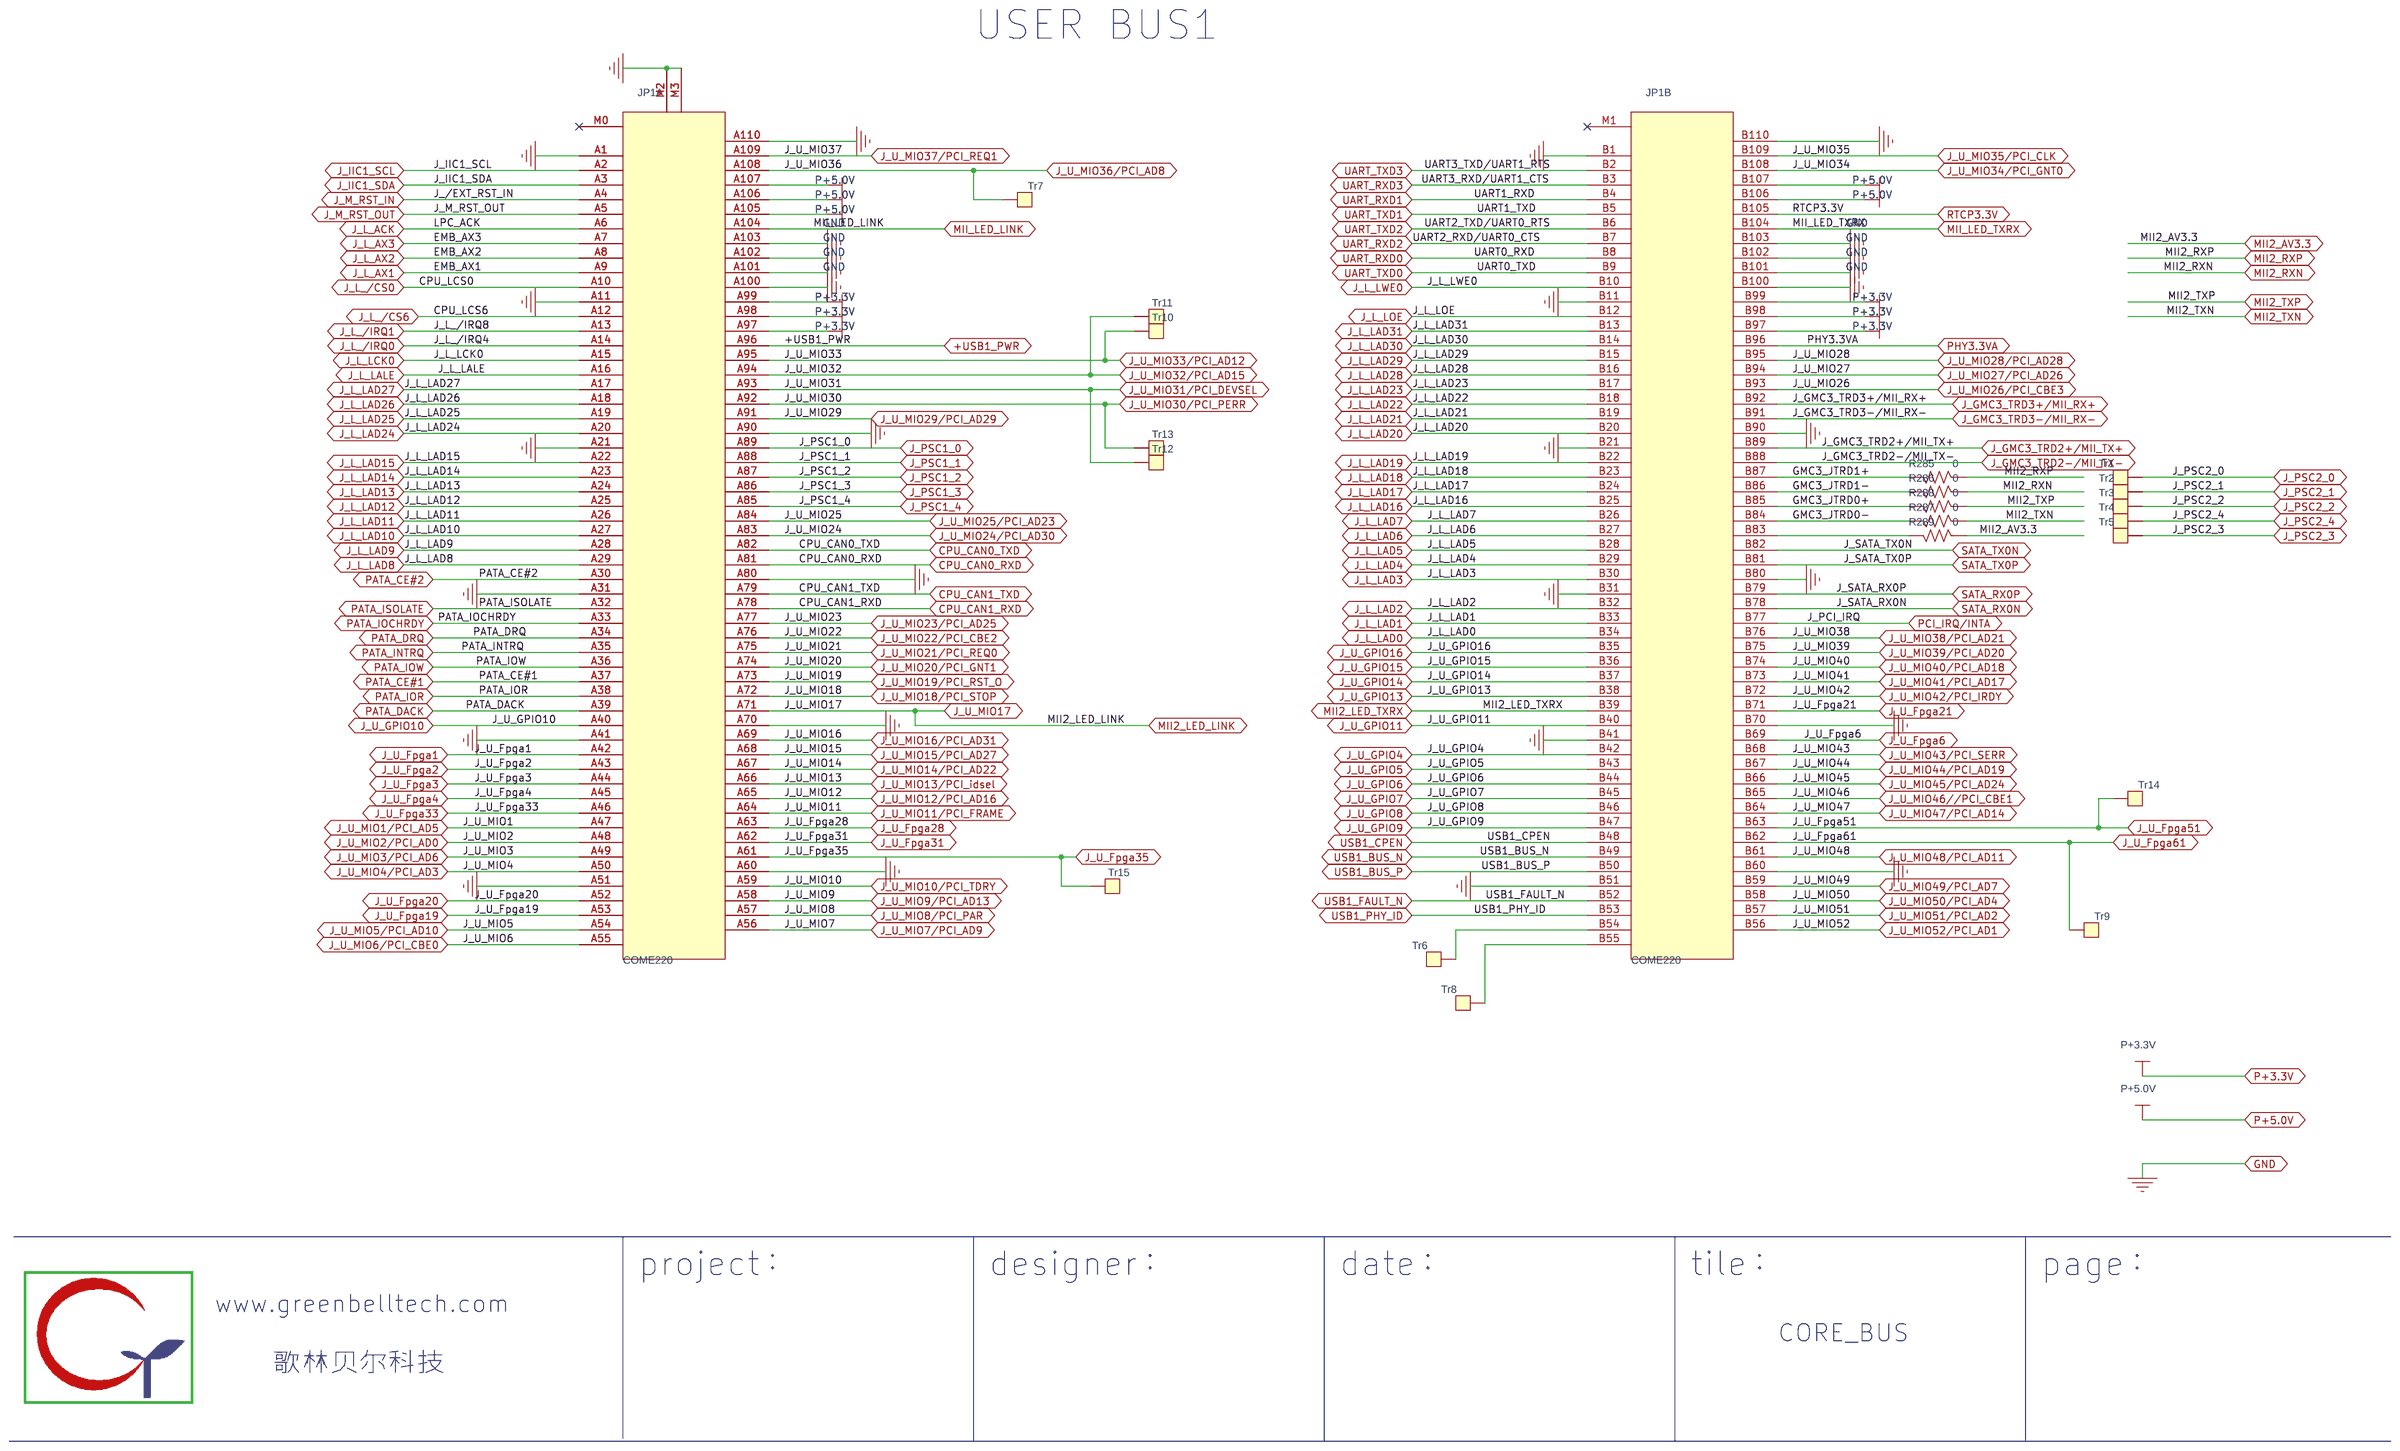
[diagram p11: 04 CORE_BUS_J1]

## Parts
sheet 04 CORE_BUS_J1
JP1  COME220  [come220]  (sections A,B)
R285  0  [R0402]
R286  0  [R0402]
R287  0  [R0402]
R288  0  [R0402]
R289  0  [R0402]
Tr1  GPHY2_MANMS  [TP-SMT1]
Tr2  GPHY2_MANMS  [TP-SMT1]
Tr3  GPHY2_MANMS  [TP-SMT1]
Tr4  GPHY2_MANMS  [TP-SMT1]
Tr5  GPHY2_MANMS  [TP-SMT1]
Tr6  GPHY2_MANMS  [TP-SMT1]
Tr7  GPHY2_MANMS  [TP-SMT1]
Tr8  GPHY2_MANMS  [TP-SMT1]
Tr9  GPHY2_MANMS  [TP-SMT1]
Tr10  GPHY2_MANMS  [TP-SMT1]
Tr11  GPHY2_MANMS  [TP-SMT1]
Tr12  GPHY2_MANMS  [TP-SMT1]
Tr13  GPHY2_MANMS  [TP-SMT1]
Tr14  GPHY2_MANMS  [TP-SMT1]
Tr15  GPHY2_MANMS  [TP-SMT1]
sheet 05 SYS_INIT
C30  0.1uF  [C0603]
C31  0.1uF  [C0603]
C33  0.1uF  [C0603]
C114  0.1uF  [C0603]
D4  LED_blue  [D0603]
D5  LED_blue  [D0603]
D6  LED_blue  [D0603]
D7  LED_blue  [D0603]
D9  LED_blue  [D0603]
D12  LED_blue  [D0603]
D13  LED_blue  [D0603]
J1  VBAT3.3V  [CR300]
J10  2x8 HEADER  [HDR-2x8-254S]
K3  KEY  [Krst4]
K6  KEY  [Krst4]
R4  4.7k  [R0603]
R7  100  [R0603]
R9  100  [R0603]
R10  100  [R0603]
R11  100  [R0603]
R12  100  [R0603]
R13  100  [R0603]
R14  100  [R0603]
R15  100  [R0603]
R16  100  [R0603]
R17  4.7k  [R0603]
R18  4.7k  [R0603]
R19  4.7k  [R0603]
R20  4.7k  [R0603]
R21  4.7k  [R0603]
R22  4.7k  [R0603]
R23  4.7k  [R0603]
R24  4.7k  [R0603]
R25  1K  [R0603]
R26  1K  [R0603]
R27  1K  [R0603]
R28  1K  [R0603]
R29  1K  [R0603]
R30  1K  [R0603]
R31  100  [R0603]
R32  4.7k  [R0603]
R33  33  [R0603]
R34  1K  [R0603]
R39  0 NP  [R0603]
R40  0  [R0603]
R41  0  [R0603]
R42  0  [R0603]
R43  0  [R0603]
U4  MAX811T  [SOT143]
U13  24LC02B-I/MS  [DIP8]
sheet 06 SYS_CPLD
C14  0.01uF  [C0402]
C115  0.1uF  [C0603]
C125  0.1uF  [C0603]
C126  0.1uF  [C0603]
C127  0.1uF  [C0603]
C128  0.1uF  [C0603]
C129  0.1uF  [C0603]
C130  0.1uF  [C0603]
C131  0.1uF  [C0603]
C132  0.1uF  [C0603]
C134  0.1uF  [C0603]
C135  0.1uF  [C0603]
C136  0.1uF  [C0603]
C137  0.1uF  [C0603]
C138  0.1uF  [C0603]
C139  0.1uF  [C0603]
C140  0.1uF  [C0603]
C141  0.1uF  [C0603]
C142  0.1uF  [C0603]
C143  0.1uF  [C0603]
C144  0.1uF  [C0603]
C145  0.1uF  [C0603]
C146  0.1uF  [C0603]
D14  LED_blue  [D0603]
J2  CPLD_JTAG  [SIP8]
J5  AT29LV040  [PLCC32-M]
J21  IDE40  [IDE40]
R254  470  [R0603]
R255  470  [R0603]
R269  10K  [R0402]
R270  1K  [R0402]
R271  1K  [R0402]
R272  0 NP  [R0402]
R273  10K  [R0402]
R274  10K  [R0402]
R275  10K  [R0402]
R276  10K  [R0402]
R277  10K  [R0402]
R278  10K  [R0402]
R279  10K  [R0402]
R280  10K  [R0402]
R281  0 NP  [R0603]
R282  1K  [R0402]
R283  0  [R0603]
R284  0  [R0402]
R292  0  [R0402]
R293  0  [R0402]
R294  0  [R0402]
R295  0  [R0402]
R296  0  [R0402]
R297  0  [R0402]
U31  LC4128V-5TN128I  [TQFP-128]  (sections -1,-2,-3)
U38  SN74LVCH16245ADGGR  [tssop48-dgg]
U39  SN74LVCH16245ADGGR  [tssop48-dgg]
sheet 07 MPC_LAN_PORT
C76  0.1uF  [C0603]
C77  270pF  [C0603]
C78  270pF  [C0603]
C79  0.1uF  [C0603]
C80  0.1uF  [C0603]
C81  0.1uF  [C0603]
C82  1000pF  [C1206]
C83  1000pF  [C1206]
C84  1000pF  [C1206]
C85  0.1uF  [C0603]
C86  270pF  [C0603]
C87  270pF  [C0603]
C88  0.1uF  [C0603]
C89  0.1uF  [C0603]
C90  0.1uF  [C0603]
C91  1000pF  [C1206]
J4  RJ45  [RJ45-N]
J6  RJ45  [RJ45-N]
R96  49.9  [R0603]
R97  49.9  [R0603]
R98  49.9  [R0603]
R99  49.9  [R0603]
R100  49.9  [R0603]
R101  49.9  [R0603]
R102  49.9  [R0603]
R103  49.9  [R0603]
R104  49.9  [R0603]
R105  49.9  [R0603]
R106  1k  [R0603]
R107  1k  [R0603]
R108  1k  [R0603]
R109  1k  [R0603]
R110  49.9  [R0603]
R111  49.9  [R0603]
R112  49.9  [R0603]
R113  49.9  [R0603]
R114  49.9  [R0603]
R115  49.9  [R0603]
R116  49.9  [R0603]
R117  49.9  [R0603]
R118  49.9  [R0603]
R119  49.9  [R0603]
T3  H1102MC  [sop16-50-285]
T4  H1102MC  [sop16-50-285]
sheet 08 PORT_OUT
C27  10uF  [C3216]
C36  0.1uF  [C0603]
C37  0.1uF  [C0603]
C38  0.1uF  [C0603]
C39  0.1uF  [C0603]
C40  0.1uF  [C0603]
C41  0.1uF  [C0603]
C42  0.1uF  [C0603]
C43  0.1uF  [C0603]
C44  0.1uF  [C0603]
C45  0.1uF  [C0603]
C46  0.1uF  [C0603]
C47  0.1uF  [C0603]
C48  0.1uF  [C0603]
C49  0.1uF  [C0603]
C50  0.1uF  [C0603]
C51  0.1uF  [C0603]
C52  0.1uF  [C0603]
C92  0.1uF  [C0402]
C93  0.1uF  [C0402]
C94  0.1uF  [C0402]
C95  0.1uF  [C0402]
C112  1000pF  [C1206]
C113  5pF  [C0603]
FB1  600  [L0603]
J20  RS232_ADD  [SIP8]
P1  UART0  [DB9A-x]
P2  DB9  [DB9A-x]
P6  DB9  [DB9A-x]
P8  SATA_CON  [sata-rsip7l]
P10  USB PORT  [USBX2]
R48  33  [R0603]
R49  33  [R0603]
R50  33  [R0603]
R51  33  [R0603]
R52  33  [R0603]
R53  33  [R0603]
R54  33  [R0603]
R55  33  [R0603]
R56  33  [R0603]
R57  33  [R0603]
R58  0  [R0603]
R59  100K  [R0603]
R60  0  [R0603]
R61  0  [R0603]
R62  62  [R0603]
R63  62  [R0603]
R64  120K  [R0603]
R65  62  [R0603]
R66  62  [R0603]
R67  120K  [R0603]
R69  nc  [R0603]
R70  0  [R0603]
R71  nc  [R0603]
R72  0  [R0603]
R74  1k  [R0603]
R75  100K np  [R0603]
R76  100K  [R0603]
R77  100K np  [R0603]
R256  0  [R0603]
R257  0  [R0603]
U3  MAX3232E  [SSOP16]
U6  MAX3232E  [SSOP16]
U7  MIC2506YM  [SOIC8]
U32  ZJYS51R5-2P  [ZJYS51R5-2P]
U33  TJA1051  [soic8]
U34  NUP2105  [SOT-23]
U35  ZJYS51R5-2P  [ZJYS51R5-2P]
U36  TJA1051  [soic8]
U37  NUP2105  [SOT-23]
sheet 09 PCIA_USER_S
C150  0.1uF  [C0402]
C180  0.1uF  [C0603]
C186  0.1uF  [C0603]
C187  470uF 16V  [RD150]
C188  0.1uF  [C0603]
C189  0.1uF  [C0603]
C190  0.1uF  [C0603]
C191  470uF 16V  [RD150]
C192  0.1uF  [C0603]
C193  470uF 16V  [RD150]
C195  470uF 16V  [RD150]
C196  0.1uF  [C0603]
C197  0.1uF  [C0603]
C198  0.1uF  [C0603]
P5  PCI  [CONN_PCI5V]
P7  PCI  [CONN_PCI5V]
R120  33  [R0402]
R133  33  [R0402]
R182  4.7k  [R0603]
R183  4.7k  [R0603]
R184  4.7k  [R0603]
R185  4.7k  [R0603]
R186  4.7k  [R0603]
R187  4.7k  [R0603]
R188  4.7k  np  [R0603]
R189  4.7k  [R0603]
R190  4.7k  [R0603]
R191  4.7k  [R0603]
R192  4.7k  [R0603]
R193  4.7k  [R0603]
R194  4.7k  [R0603]
R195  0  [R0603]
R196  0  [R0603]
R197  4.7k  [R0603]
R198  4.7k  [R0603]
R199  0  [R0603]
R200  0  [R0603]
R201  0  [R0603]
R202  0 np  [R0603]
R203  0  [R0603]
R204  0  [R0603]
U28  553SCMG  [DFN-8]
sheet 10 USER_PORT_M
J7  USER_Define  [SIP8]
J11  2x8 HEADER  [HDR-2x8-254S]
J13  2x8 HEADER  [HDR-2x8-254S]
R290  0  [R0402]
R291  0  [R0402]
sheet 11 POWER_IN   CCC
C2  220uF 16V  [CD220]
C3  220uF 16V  [CD220]
C9  470uF 35V  [RD200]
C10  470uF 35V  [RD200]
C12  220uF 16V  [CD220]
C13  10uF 16V  [C3216]
C101  10uF  [C0603]
C102  0.1uF  [C0603]
C103  22uF  [C0805]
C104  0.1uF  [C0603]
C105  0.1uF  [C0603]
C106  0.1uF  [C0603]
C107  0.1uF  [C0603]
C108  0.1uF  [C0603]
C109  0.1uF  [C0603]
C110  22uF  [C0805]
C111  22uF  [C0805]
C116  22uF  [C0805]
C117  0.1uF  [C0603]
C118  220uF 16V  [CD220]
C119  220uF 16V  [CD220]
C120  220uF 16V  [CD220]
C121  220uF 16V  [CD220]
C122  0.1uF  [C0603]
C123  22uF  [C0805]
C124  0.1uF  [C0603]
C133  22uF  [C0805]
C147  22uF  [C0805]
C148  0.1uF  [C0603]
C149  22uF  [C0805]
C194  470uF 16V  [RD150]
D0  LED_blue  [D0603]
D10  LED_blue  [D0603]
D11  LED_blue  [D0603]
F0  F  [FIDUCIAL_I1MM_O3MM_DRA]
F1  F  [FIDUCIAL_I1MM_O3MM_DRA]
F2  F  [FIDUCIAL_I1MM_O3MM_DRA]
F3  F  [FIDUCIAL_I1MM_O3MM_DRA]
J3  FAN+12V  [JSIP2]
J12  4 HEADER  [dc-pin]
J19  4 HEADER  [atx-dc4]
L6  2A/100  [L1210]
L7  2A/100  [L1210]
L8  2A/100  [L1210]
L9  2A/100  [L1210]
L10  2A/100  [L1210]
L11  BLM11601SPT  [L0603]
L12  2A/100  [L1210]
L13  2A/100  [L1210]
L14  2A/100  [L1210]
L15  2A/100  [L1210]
L16  2A/100  [L1210]
R225  18k  [R0603]
R226  3k  [R0603]
R227  18k  [R0603]
R228  3k  [R0603]
R247  330  [R0603]
R248  1.5k  [R0603]
R249  1k  [R0603]
R250  1k  [R0603]
R251  1k  [R0603]
R252  2k  [R0603]
R253  3.3k  [R0603]
U11  PTH12050W  [EUU6]
U12  PTH12050W  [EUU6]
U22  ams1084  [TO-263]
U23  ams1084  [TO-223]

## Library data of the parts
JP1 = COME220J_0
R182-R204 R247-R255 R269-R297 = R
Tr1-Tr15 = T_POINT_S
C30 C31 C33 C36-C52 C76-C95 C101-C117 C122-C150 C180 C186 C188-C190 C192 C196-C198 = C_0.1uF_16V_10%_0402
D0 D4-D7 D9-D14 = HLMP-1700_1: Color: Default; Load: LOAD
J1 J12 J19 = 4_HEADER
J10 J11 J13 = CON_HDR_2x8_M_VT_TH_2.54: SPEC: MPC_JTAG
K3 K6 = SW_TACT-SPST-2
FB1 R4 R7 R9-R34 R39-R43 R48-R67 R69-R72 R74-R77 R96-R119 R225-R228 R256 R257 = RESISTOR: BOM Description: CHIP RES49.9R 1% 200PPM 0402 1/16W; Component Type: 22.1K 1%; Load: NO LOAD; Mfg.: Yageo; Mfg. P/N: RC0402FRG 49R9; Part Number: RES_49.9R_1%_0402
U4 = MAX811T
U13 = 74HCT74_2
C14 = C_18pF_50V_10%_0603
J2 J7 J20 = CONN_TRBLK_8
J5 = AT29040_0
J21 = CON40A
U31 = LC4128V-TN128
U38 U39 = SN74LVCH16245A
J4 J6 = RJ45-1X1-L: PartNumber: *0202075
T3 T4 = H1012_0: Load: LOAD
C27 = E_33uF_6.3V_20%_A3216
P1 P2 P6 = CONNECTOR_DB9_3: CLASS: IO
P8 = SATA_PORT_2
P10 = CON12_2
U3 U6 = MAX232E_0
U7 = MIC2506YM
U32 U35 = ZJYS51R5-2P
U33 U36 = max3050
U34 U37 = NUP2105
C2 C3 C9 C10 C12 C13 C118-C121 C187 C191 C193-C195 = E_100uF_6.3V_20%_B3528: SPEC: C3528
P5 P7 = PCI_CONNECTOR_1: CLASS: IO
R120 R133 = R_75_1_16W_5%_0603: SPEC: 0402
U28 = 553SCMG
F0-F3 = CON1
J3 = B2S
L6-L10 L12-L16 = L_BEAD_60_OHM_0603
L11 = INDUCTOR: CLASS: Discrete
U11 U12 = PTH12050W
U22 U23 = ams1084

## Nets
+2.5V: C13.1 C124.2 C147.2 R227.2 U23.2(Vout) U23.4(Pad)
+3.3V: C2.1 C3.1 C31.2 C33.2 C44.2 C45.2 C108.2 C109.2 C115.2 C125.2 C126.2 C127.2 C128.2 C129.2 C130.2 C131.2 C132.2 C134.2 C135.2 C136.2 C137.2 C138.2 C139.2 C140.2 C141.2 C142.2 C143.2 C150.2 C180.2 C186.2 C187.1 C188.2 C195.1 C196.2 C197.2 D11.A(ANODE) J2.1 J5.32(VCC) L7.1(A) L8.1(A) L10.1(A) L15.2(B) L16.2(B) P5.A14(3.3Vaux) P5.A21(+3.3V11) P5.A27(+3.3V12) P5.A33(+3.3V13) P5.A39(+3.3V14) P5.A45(+3.3V) P5.A53(+3.3V15) P5.B25(+3.3V2) P5.B31(+3.3V3) P5.B36(+3.3V4) P5.B41(+3.3V5) P5.B43(+3.3V6) P5.B54(+3.3V7) P7.A14(3.3Vaux) P7.A21(+3.3V11) P7.A27(+3.3V12) P7.A33(+3.3V13) P7.A39(+3.3V14) P7.A45(+3.3V) P7.A53(+3.3V15) P7.B25(+3.3V2) P7.B31(+3.3V3) P7.B36(+3.3V4) P7.B41(+3.3V5) P7.B43(+3.3V6) P7.B54(+3.3V7) R4.1 R17.1 R18.1 R19.1 R20.1 R21.1 R22.1 R23.1 R24.1 R25.1 R26.1 R27.1 R28.1 R29.1 R30.1 R32.1 R34.1 R39.1 R41.1 R59.2 R70.1 R72.1 R75.2 R106.2 R107.2 R108.2 R109.2 R183.1 R184.1 R186.1 R187.1 R188.2 R191.1 R194.1 R197.1 R198.1 R273.2 R281.2 U3.16(VCC) U4.4(VCC) U6.16(VCC) U13.8(VCC) U28.1(VDD) U28.8(OE) U31.3(VCCO(BANK0)) U31.17(VCCO(BANK0)) U31.30(VCCO(BANK0)) U31.32(VCC) U31.41(VCCO(BANK0)) U31.51(VCC) U31.58(VCCO(BANK1)) U31.67(VCCO(BANK1)) U31.81(VCCO(BANK1)) U31.94(VCCO(BANK1)) U31.96(VCC) U31.105(VCCO(BANK1)) U31.115(VCC) U31.122(VCCO(BANK0)) U38.31(Vcc2A) U38.42(Vcc1A) U39.31(Vcc2A) U39.42(Vcc1A)
+5.0V: C27.1 C46.1 C48.2 C51.2 C106.2 C107.2 C119.1 C120.1 C148.2 C189.2 C190.2 C191.1 C192.2 C193.1 C198.2 D0.A(ANODE) L6.1(A) L9.1(A) L12.1(A) L13.2(B) L14.2(B) P5.A5(+5V5) P5.A8(+5V6) P5.A61(+5V7) P5.A62(+5V8) P5.B5(+5V1) P5.B6(+5V2) P5.B61(+5V3) P5.B62(+5V4) P7.A5(+5V5) P7.A8(+5V6) P7.A61(+5V7) P7.A62(+5V8) P7.B5(+5V1) P7.B6(+5V2) P7.B61(+5V3) P7.B62(+5V4) R69.1 R71.1 R76.2 R77.2 R283.1 U7.7(IN) U23.3(Vin) U33.3(VCC) U36.3(VCC)
+12V: C9.1 C10.1 C102.2 C103.2 C105.2 C110.2 C116.2 C117.2 C122.2 D10.A(ANODE) J11.2 J11.4 J12.1 J13.2 J13.4 J19.1 L11.1 P5.A2(+12V) P7.A2(+12V) U11.2(Track) U11.3(Vin) U12.2(Track) U12.3(Vin) U22.3(Vin)
-12V: P5.B1(-12V) P7.B1(-12V)
GND: C2.2 C3.2 C9.2 C10.2 C12.2 C13.2 C14.2 C27.2 C30.2 C31.1 C33.1 C38.2 C39.2 C40.2 C41.2 C44.1 C45.1 C46.2 C47.2 C48.1 C49.1 C50.2 C51.1 C52.1 C76.2 C79.1 C80.1 C81.1 C85.2 C88.1 C89.1 C90.1 C101.1 C102.1 C103.1 C104.1 C105.1 C106.1 C107.1 C108.1 C109.1 C110.1 C111.1 C113.2 C114.1 C115.1 C116.1 C117.1 C118.2 C119.2 C120.2 C121.2 C122.1 C123.1 C124.1 C125.1 C126.1 C127.1 C128.1 C129.1 C130.1 C131.1 C132.1 C133.1 C134.1 C135.1 C136.1 C137.1 C138.1 C139.1 C140.1 C141.1 C142.1 C143.1 C144.1 C145.1 C146.1 C147.1 C148.1 C149.1 C150.1 C180.1 C186.1 C187.2 C188.1 C189.1 C190.1 C191.2 C192.1 C193.2 C194.2 C195.2 C196.1 C197.1 C198.1 FB1.2 J1.2 J2.7 J3.1 J5.16(GND) J7.1 J7.4 J7.5 J7.8 J11.1 J11.3 J11.5 J12.2 J13.1 J13.3 J13.5 J19.2 J19.3 J20.3 J20.6 J21.2 J21.19 J21.22 J21.24 J21.26 J21.28 J21.30 J21.40 JP1.A1 JP1.A11 JP1.A21 JP1.A31 JP1.A41 JP1.A51 JP1.A60 JP1.A70 JP1.A80 JP1.A90 JP1.A100 JP1.A101 JP1.A102 JP1.A103 JP1.A110 JP1.B1 JP1.B11 JP1.B21 JP1.B31 JP1.B41 JP1.B51 JP1.B60 JP1.B70 JP1.B80 JP1.B90 JP1.B100 JP1.B101 JP1.B102 JP1.B103 JP1.B110 JP1.M2 JP1.M3 P1.5 P2.3 P5.A12(GND19) P5.A13(GND20) P5.A18(GND12) P5.A24(GND13) P5.A30(GND14) P5.A35(GND15) P5.A37(GND16) P5.A42(GND17) P5.A48(GND18) P5.A56(GND21) P5.B3(GND1) P5.B12(GND9) P5.B13(GND10) P5.B15(GND2) P5.B17(GND3) P5.B22(GND4) P5.B28(GND5) P5.B34(GND6) P5.B38(GND7) P5.B46(GND8) P5.B57(GND11) P6.3 P7.A12(GND19) P7.A13(GND20) P7.A18(GND12) P7.A24(GND13) P7.A30(GND14) P7.A35(GND15) P7.A37(GND16) P7.A42(GND17) P7.A48(GND18) P7.A56(GND21) P7.B3(GND1) P7.B12(GND9) P7.B13(GND10) P7.B15(GND2) P7.B17(GND3) P7.B22(GND4) P7.B28(GND5) P7.B34(GND6) P7.B38(GND7) P7.B46(GND8) P7.B57(GND11) P8.00(F1) P8.1(GND) P8.01(F2) P8.4(GND) P8.7(GND) R7.2 R9.2 R10.2 R11.2 R12.2 R13.2 R14.2 R15.2 R16.2 R31.2 R40.2 R42.1 R43.1 R58.2 R64.2 R67.2 R74.1 R182.2 R185.2 R189.2 R190.2 R192.2 R193.2 R226.2 R228.2 R247.2 R250.2 R251.2 R252.2 R253.2 R269.1 R270.1 R271.1 R274.1 R275.1 U3.15(GND) U4.1(GND) U6.15(GND) U7.6(GND) U11.1(GND) U12.1(GND) U13.4(GND) U28.4(GND) U31.1(GND) U31.10(GND(BANK0)) U31.24(GND(BANK0)) U31.33(GND) U31.40(GND(BANK0)) U31.49(GND(BANK1)) U31.59(GND(BANK1)) U31.65(GND) U31.74(GND(BANK1)) U31.88(GND(BANK1)) U31.97(GND) U31.104(GND(BANK1)) U31.113(GND(BANK0)) U31.123(GND(BANK0)) U33.2(GND) U34.3 U36.2(GND) U37.3 U38.4(GND1) U38.10(GND2) U38.15(GND3) U38.21(GND4) U38.28(GND5) U38.34(GND6) U38.39(GND7) U38.45(GND8) U38.48(1/OE) U39.4(GND1) U39.10(GND2) U39.15(GND3) U39.21(GND4) U39.24(2DIR) U39.28(GND5) U39.34(GND6) U39.39(GND7) U39.45(GND8) U39.48(1/OE)
GND_EARTH: C82.1 C83.1 C84.1 C91.1 C112.1 C113.1 P2.10 P2.11 P6.10 P6.11 P10.9 P10.10 P10.11 P10.12
+USB1_PWR: JP1.A96 P10.1 R76.1 U7.8(OUTA)
+USB2_PWR: P10.5 R77.1 U7.5(OUTB)
CAN0_BUS_H: P6.7 R63.1 U32.1 U34.1
CAN0_BUS_L: P6.2 R62.1 U32.2 U34.2
CAN0_H: U32.4 U33.7(CANH)
CAN0_L: U32.3 U33.6(CANL)
CAN1_BUS_H: P2.7 R66.1 U35.1 U37.1
CAN1_BUS_L: P2.2 R65.1 U35.2 U37.2
CAN1_H: U35.4 U36.7(CANH)
CAN1_L: U35.3 U36.6(CANL)
CPLD_LED0: D4.K(CATHODE) U31.63(E12)
CPLD_TCK: J2.8 U31.31(TCK)
CPLD_TDI: J2.3 U31.2(TDI)
CPLD_TDO: J2.2 U31.95(TDO)
CPLD_TMS: J2.6 U31.66(TMS)
CPU_CAN0_RXD: JP1.A81 U33.4(RXD)
CPU_CAN0_TXD: JP1.A82 U33.1(TXD)
CPU_CAN1_RXD: JP1.A78 U36.4(RXD)
CPU_CAN1_TXD: JP1.A79 U36.1(TXD)
EEPROM_CS: J5.22(~{CE}) U31.21(C10)
F_LOE: J5.24(~{OE}) U31.18(C14)
G1_MCT1: T3.15(TX-CT)
G1_MCT2: T3.10(RX-CT)
G2_MCT1: T4.15(TX-CT)
G2_MCT2: T4.10(RX-CT)
GMC1_LINE_TRD0+: J4.1(A1) T3.16(TX+)
GMC1_LINE_TRD0-: J4.2(A2) T3.14(TX-)
GMC1_LINE_TRD1+: J4.3(A3) T3.11(RX+)
GMC1_LINE_TRD1-: J4.6(A6) T3.9(RX-)
GMC1_LINE_TRD2+: J4.4(A4) R116.1
GMC1_LINE_TRD2-: J4.5(A5) R115.1
GMC1_LINE_TRD3+: J4.7(A7) R117.1
GMC1_LINE_TRD3-: J4.8(A8) R118.1
GMC2_LINE_TRD0+: J6.1(A1) T4.16(TX+)
GMC2_LINE_TRD0-: J6.2(A2) T4.14(TX-)
GMC2_LINE_TRD1+: J6.3(A3) T4.11(RX+)
GMC2_LINE_TRD1-: J6.6(A6) T4.9(RX-)
GMC2_LINE_TRD2+: J6.4(A4) R101.1
GMC2_LINE_TRD2-: J6.5(A5) R102.1
GMC2_LINE_TRD3+: J6.7(A7) R104.1
GMC2_LINE_TRD3-: J6.8(A8) R103.1
GMC3_JTRD0+: JP1.B85 R288.2
GMC3_JTRD0-: JP1.B84 R287.2
GMC3_JTRD1+: JP1.B87 R285.2
GMC3_JTRD1-: JP1.B86 R286.2
HPCI+VIO: P5.A10(+V_IO5) P5.A16(+V_IO4) P5.A59(+V_IO3) P5.B19(+V_IO1) P5.B59(+V_IO2) P7.A10(+V_IO5) P7.A16(+V_IO4) P7.A59(+V_IO3) P7.B19(+V_IO1) P7.B59(+V_IO2)
HPCI_IDSEL#1: P5.A26(IDSEL) R195.1
HPCI_IDSEL#2: P7.A26(IDSEL) R203.1
HPCI_M66EN: P5.B49(M66EN) P7.B49(M66EN) R188.1 R189.1
J_GMC3_TRD2+/MII_TX+: JP1.B89 R112.2 T3.1(TD+)
J_GMC3_TRD2-/MII_TX-: JP1.B88 R113.2 T3.3(TD-)
J_GMC3_TRD3+/MII_RX+: C86.1 JP1.B92
J_GMC3_TRD3-/MII_RX-: C87.1 JP1.B91
J_IIC1_SCL: JP1.A2 R199.1 U13.6(SCL)
J_IIC1_SDA: JP1.A3 R200.1 U13.5(SDA)
J_L_/CS0: JP1.A10 U31.85(G10)
J_L_/CS6: JP1.A12 U31.84(G12)
J_L_/IRQ0: JP1.A14 R196.2 U31.83(G13)
J_L_/IRQ1: C114.2 JP1.A13 K6.1 K6.2 R4.2 R204.2
J_L_ACK: JP1.A6 U31.90(G5)
J_L_AX1: JP1.A9 U31.86(G9) U39.41(1A5)
J_L_AX2: JP1.A8 U31.87(G8) U39.40(1A6)
J_L_AX3: JP1.A7 U31.89(G6)
J_L_LAD0: JP1.B34 U31.91(G4) U38.47(1A1)
J_L_LAD1: JP1.B33 U31.92(G2) U38.46(1A2)
J_L_LAD2: JP1.B32 U31.93(G0) U38.44(1A3)
J_L_LAD3: JP1.B30 U31.98(H14) U38.43(1A4)
J_L_LAD4: JP1.B29 U31.99(H13) U38.41(1A5)
J_L_LAD5: JP1.B28 U31.100(H12) U38.40(1A6)
J_L_LAD6: JP1.B27 U31.101(H10) U38.38(1A7)
J_L_LAD7: JP1.B26 U31.102(H9) U38.37(1A8)
J_L_LAD8: JP1.A29 U31.68(F0) U38.36(2A1)
J_L_LAD9: JP1.A28 U31.69(F1) U38.35(2A2)
J_L_LAD10: JP1.A27 U31.70(F2) U38.33(2A3)
J_L_LAD11: JP1.A26 U31.71(F4) U38.32(2A4)
J_L_LAD12: JP1.A25 U31.72(F5) U38.30(2A5)
J_L_LAD13: JP1.A24 U31.73(F6) U38.29(2A6)
J_L_LAD14: JP1.A23 U31.75(F8) U38.27(2A7)
J_L_LAD15: JP1.A22 U31.76(F9) U38.26(2A8)
J_L_LAD16: JP1.B25 U31.103(H8)
J_L_LAD17: JP1.B24 U31.106(H6)
J_L_LAD18: JP1.B23 U31.107(H5)
J_L_LAD19: JP1.B22 U31.108(H4)
J_L_LAD20: JP1.B20 U31.109(H2)
J_L_LAD21: JP1.B19 U31.110(H1)
J_L_LAD22: JP1.B18 U31.117(A1)
J_L_LAD23: JP1.B17 U31.118(A2)
J_L_LAD24: JP1.A20 U31.77(F10)
J_L_LAD25: JP1.A19 U31.78(F12)
J_L_LAD26: JP1.A18 U31.79(F13)
J_L_LAD27: JP1.A17 U31.80(F14)
J_L_LAD28: JP1.B16 U31.119(A4)
J_L_LAD29: JP1.B15 U31.120(A5)
J_L_LAD30: JP1.B14 U31.121(A6)
J_L_LAD31: JP1.B13 U31.124(A8)
J_L_LALE: JP1.A16 U31.82(G14) U39.43(1A4)
J_L_LCK0: JP1.A15 U31.50(CLK2/I)
J_L_LOE: JP1.B12 U31.111(H0/GOE1)
J_L_LWE0: JP1.B10 U31.125(A9)
J_M_RST_IN: JP1.A4 R33.1
J_M_RST_OUT: JP1.A5 R202.1 R284.1 U31.114(CLK0/I)
J_PSC1_0: J13.7 JP1.A89
J_PSC1_1: J13.9 JP1.A88
J_PSC1_2: J13.11 JP1.A87
J_PSC1_3: J13.13 JP1.A86
J_PSC1_4: J13.15 JP1.A85
J_PSC2_0: J11.7 Tr1.1(TP)
J_PSC2_1: J11.9 Tr2.1(TP)
J_PSC2_2: J11.11 Tr3.1(TP)
J_PSC2_3: J11.13 Tr5.1(TP)
J_PSC2_4: J11.15 Tr4.1(TP)
J_U_Fpga1: J13.6 JP1.A42
J_U_Fpga2: J13.8 JP1.A43
J_U_Fpga3: J13.10 JP1.A44
J_U_Fpga4: J13.12 JP1.A45
J_U_Fpga6: J11.14 JP1.B69
J_U_Fpga19: J13.16 JP1.A53
J_U_Fpga20: J11.8 JP1.A52
J_U_Fpga21: J11.6 JP1.B71
J_U_Fpga28: J11.10 JP1.A63
J_U_Fpga31: J11.12 JP1.A62
J_U_Fpga33: J13.14 JP1.A46
J_U_Fpga35: J11.16 JP1.A61 Tr15.1(TP)
J_U_Fpga51: J7.2 JP1.B63 Tr14.1(TP)
J_U_Fpga61: J7.3 JP1.B62 Tr9.1(TP)
J_U_GPIO4: J10.9 JP1.B42 R21.2
J_U_GPIO5: J10.7 JP1.B43 R20.2
J_U_GPIO6: J10.5 JP1.B44 R19.2
J_U_GPIO7: J10.3 JP1.B45 R18.2
J_U_GPIO8: D5.K(CATHODE) JP1.B46
J_U_GPIO9: D6.K(CATHODE) JP1.B47
J_U_GPIO10: J10.13 JP1.A40 R23.2
J_U_GPIO11: J10.11 JP1.B40 R22.2
J_U_GPIO13: D7.K(CATHODE) JP1.B38
J_U_GPIO14: D9.K(CATHODE) JP1.B37
J_U_GPIO15: D12.K(CATHODE) JP1.B36
J_U_GPIO16: D13.K(CATHODE) JP1.B35
J_U_MIO1/PCI_AD5: JP1.A47 P5.B55(AD[05]) P7.B55(AD[05])
J_U_MIO2/PCI_AD0: JP1.A48 P5.A58(AD[00]) P7.A58(AD[00])
J_U_MIO3/PCI_AD6: JP1.A49 P5.A54(AD[06]) P7.A54(AD[06])
J_U_MIO4/PCI_AD3: JP1.A50 P5.B56(AD[03]) P7.B56(AD[03])
J_U_MIO5/PCI_AD10: JP1.A54 P5.B48(AD[10]) P7.B48(AD[10])
J_U_MIO6/PCI_CBE0: JP1.A55 P5.A52(C/BE[0]#) P7.A52(C/BE[0]#)
J_U_MIO7/PCI_AD9: JP1.A56 P5.A49(AD[09]) P7.A49(AD[09])
J_U_MIO8/PCI_PAR: JP1.A57 P5.A43(PAR) P7.A43(PAR)
J_U_MIO9/PCI_AD13: JP1.A58 P5.A46(AD[13]) P7.A46(AD[13])
J_U_MIO10/PCI_TDRY: JP1.A59 P5.A36(TRDY#) P7.A36(TRDY#)
J_U_MIO11/PCI_FRAME: JP1.A64 P5.A34(FRAME#) P7.A34(FRAME#)
J_U_MIO12/PCI_AD16: JP1.A65 P5.A32(AD[16]) P7.A32(AD[16])
J_U_MIO13/PCI_idsel: JP1.A66 R190.1
J_U_MIO14/PCI_AD22: JP1.A67 P5.A28(AD[22]) P7.A28(AD[22]) R203.2
J_U_MIO15/PCI_AD27: JP1.A68 P5.B23(AD[27]) P7.B23(AD[27])
J_U_MIO16/PCI_AD31: JP1.A69 P5.B20(AD[31]) P7.B20(AD[31])
J_U_MIO17: J6.9(A9) JP1.A71
J_U_MIO18/PCI_STOP: JP1.A72 P5.A38(STOP#) P7.A38(STOP#)
J_U_MIO19/PCI_RST_O: JP1.A73 R201.1
J_U_MIO20/PCI_GNT1: JP1.A74 P7.A17(GNT#) R290.1
J_U_MIO21/PCI_REQ0: JP1.A75 P5.B18(REQ#)
J_U_MIO22/PCI_CBE2: JP1.A76 P5.B33(C/BE[2]#) P7.B33(C/BE[2]#)
J_U_MIO23/PCI_AD25: JP1.A77 P5.B24(AD[25]) P7.B24(AD[25])
J_U_MIO24/PCI_AD30: JP1.A83 P5.A20(AD[30]) P7.A20(AD[30])
J_U_MIO25/PCI_AD23: JP1.A84 P5.B27(AD[23]) P7.B27(AD[23]) R195.2
J_U_MIO26/PCI_CBE3: JP1.B93 P5.B26(C/BE[3]#) P7.B26(C/BE[3]#)
J_U_MIO27/PCI_AD26: JP1.B94 P5.A23(AD[26]) P7.A23(AD[26])
J_U_MIO28/PCI_AD28: JP1.B95 P5.A22(AD[28]) P7.A22(AD[28])
J_U_MIO29/PCI_AD29: JP1.A91 P5.B21(AD[29]) P7.B21(AD[29])
J_U_MIO30/PCI_PERR: JP1.A92 P5.B40(PERR#) P7.B40(PERR#) Tr13.1(TP)
J_U_MIO31/PCI_DEVSEL: JP1.A93 P5.B37(DEVSEL#) P7.B37(DEVSEL#) Tr12.1(TP)
J_U_MIO32/PCI_AD15: JP1.A94 P5.A44(AD[15]) P7.A44(AD[15]) Tr11.1(TP)
J_U_MIO33/PCI_AD12: JP1.A95 P5.B47(AD[12]) P7.B47(AD[12]) Tr10.1(TP)
J_U_MIO34/PCI_GNT0: JP1.B108 P5.A17(GNT#)
J_U_MIO35/PCI_CLK: JP1.B109 U28.5(ICLK)
J_U_MIO36/PCI_AD8: JP1.A108 P5.B52(AD[08]) P7.B52(AD[08]) Tr7.1(TP)
J_U_MIO37/PCI_REQ1: JP1.A109 P7.B18(REQ#) R291.1
J_U_MIO38/PCI_AD21: JP1.B76 P5.B29(AD[21]) P7.B29(AD[21])
J_U_MIO39/PCI_AD20: JP1.B75 P5.A29(AD[20]) P7.A29(AD[20])
J_U_MIO40/PCI_AD18: JP1.B74 P5.A31(AD[18]) P7.A31(AD[18])
J_U_MIO41/PCI_AD17: JP1.B73 P5.B32(AD[17]) P7.B32(AD[17])
J_U_MIO42/PCI_IRDY: JP1.B72 P5.B35(IRDY#) P7.B35(IRDY#)
J_U_MIO43/PCI_SERR: JP1.B68 P5.B42(SERR#) P7.B42(SERR#)
J_U_MIO44/PCI_AD19: JP1.B67 P5.B30(AD[19]) P7.B30(AD[19])
J_U_MIO45/PCI_AD24: JP1.B66 P5.A25(AD[24]) P7.A25(AD[24])
J_U_MIO46//PCI_CBE1: JP1.B65 P5.B44(C/BE[1]#) P7.B44(C/BE[1]#)
J_U_MIO47/PCI_AD14: JP1.B64 P5.B45(AD[14]) P7.B45(AD[14])
J_U_MIO48/PCI_AD11: JP1.B61 P5.A47(AD[11]) P7.A47(AD[11])
J_U_MIO49/PCI_AD7: JP1.B59 P5.B53(AD[07]) P7.B53(AD[07])
J_U_MIO50/PCI_AD4: JP1.B58 P5.A55(AD[04]) P7.A55(AD[04])
J_U_MIO51/PCI_AD2: JP1.B57 P5.A57(AD[02]) P7.A57(AD[02])
J_U_MIO52/PCI_AD1: JP1.B56 P5.B58(AD[01]) P7.B58(AD[01])
ks: C83.2 C84.2 J4.13(PGND1) J4.14(PGND2) J6.13(PGND1) J6.14(PGND2)
L_D0: J5.13(D0) U31.37(D10)
L_D1: J5.14(D1) U31.36(D12)
L_D2: J5.15(D2) U31.35(D13)
L_D3: J5.17(D3) U31.29(C0)
L_D4: J5.18(D4) U31.27(C4)
L_D5: J5.19(D5) U31.26(C5)
L_D6: J5.20(D6) U31.23(C8)
L_D7: J5.21(D7) U31.20(C12)
Laddr0: J5.12(A0) U31.28(C2)
Laddr1: J5.11(A1) U31.34(D14)
Laddr2: J5.10(A2) U31.22(C9)
Laddr3: J5.9(A3) U31.25(C6)
Laddr4: J5.8(A4) U31.15(B13)
Laddr5: J5.7(A5) U31.19(C13)
Laddr6: J5.6(A6) U31.8(B5)
Laddr7: J5.5(A7) U31.12(B9)
Laddr8: J5.27(A8) U31.9(B6)
Laddr9: J5.26(A9) U31.14(B12)
Laddr10: J5.23(A10) U31.16(B14)
Laddr11: J5.25(A11) U31.13(B10)
Laddr12: J5.4(A12) U31.126(A10)
Laddr13: J5.28(A13) U31.11(B8)
Laddr14: J5.29(A14) U31.6(B2)
Laddr15: J5.3(A15) U31.7(B4)
Laddr16: J5.2(A16) U31.128(A14)
Laddr17: J5.30(A17) U31.127(A12)
Laddr18: J5.1(A18) U31.4(B0)
LBS_LWE0: J5.31(~{WE}) U31.5(B1)
MII2_AV3.3: C80.2 R289.1 T4.2(TD-CT)
MII2_C_RXN: C78.2 R97.2 T4.8(RD-CT)
MII2_C_RXP: C77.2 R96.2 T4.6(RD+)
MII2_LED_TXRX: J6.11(A11) JP1.B39
MII2_RXN: C78.1 R286.1
MII2_RXP: C77.1 R285.1
MII2_TXN: R99.2 R287.1 T4.3(TD-)
MII2_TXP: R98.2 R288.1 T4.1(TD+)
MII_C_RXN: C87.2 R111.2 T3.8(RD-CT)
MII_C_RXP: C86.2 R110.2 T3.6(RD+)
MII_LED_LINK: J4.9(A9) JP1.A104
MII_LED_TXRX: J4.11(A11) JP1.B104
P+3.3V: C111.2 C123.2 JP1.A97 JP1.A98 JP1.A99 JP1.B97 JP1.B98 JP1.B99 L15.1(A) L16.1(A)
P+5.0V: C149.2 C194.1 JP1.A105 JP1.A106 JP1.A107 JP1.B106 JP1.B107 L13.1(A) L14.1(A)
PATA_AD0: J21.17 U38.2(1B1)
PATA_AD1: J21.15 U38.3(1B2)
PATA_AD2: J21.13 U38.5(1B3)
PATA_AD3: J21.11 U38.6(1B4)
PATA_AD4: J21.9 U38.8(1B5)
PATA_AD5: J21.7 U38.9(1B6)
PATA_AD6: J21.5 U38.11(1B7)
PATA_AD7: J21.3 R269.2 U38.12(1B8)
PATA_AD8: J21.4 U38.13(2B1)
PATA_AD9: J21.6 U38.14(2B2)
PATA_AD10: J21.8 U38.16(2B3)
PATA_AD11: J21.10 U38.17(2B4)
PATA_AD12: J21.12 U38.19(2B5)
PATA_AD13: J21.14 U38.20(2B6)
PATA_AD14: J21.16 U38.22(2B7)
PATA_AD15: J21.18 U38.23(2B8)
PATA_C_DASP#: D14.K(CATHODE) J21.39 R255.2
PATA_C_IOCS16#: J21.32 R282.2
PATA_CE#1: JP1.A37 U39.38(1A7)
PATA_CE#2: JP1.A30 U39.37(1A8)
PATA_CS0#: J21.37 R278.1 U39.11(1B7)
PATA_CS1#: J21.38 R279.1 U39.12(1B8)
PATA_DA0: J21.35 U39.6(1B4)
PATA_DA1: J21.33 U39.8(1B5)
PATA_DA2: J21.36 U39.9(1B6)
PATA_DACK: JP1.A39 U39.44(1A3)
PATA_DACK_C: J21.29 U39.5(1B3)
PATA_DRQ: JP1.A34 U39.35(2A2)
PATA_DRQ_C: J21.21 R275.2 U39.14(2B2)
PATA_INTRQ: JP1.A35 U39.33(2A3)
PATA_INTRQ_C: J21.31 R274.2 R297.1 U39.16(2B3)
PATA_IOCHRDY: JP1.A33 U39.36(2A1)
PATA_IOCHRDY_C: J21.27 R280.1 R293.1 U39.13(2B1)
PATA_IOR: JP1.A38 U39.46(1A2)
PATA_IOR_C: J21.25 R277.1 R294.1 U39.3(1B2)
PATA_IOW: JP1.A36 U39.47(1A1)
PATA_IOW_C: J21.23 R276.1 R295.1 U39.2(1B1)
PATA_ISOLATE: JP1.A32 R272.1 U38.1(1DIR) U38.24(2DIR)
PATA_VDD: C144.2 C145.2 C146.2 R254.1 R255.1 R276.2 R277.2 R278.2 R279.2 R280.2 R281.1 R282.1 R283.2 U38.7(Vcc1B) U38.18(Vcc2B) U39.7(Vcc1B) U39.18(Vcc2B)
PCI_CLK1: P5.B16(CLK) R133.1
PCI_CLK2: P7.B16(CLK) R120.1
PCI_INT1: P5.A6(INTA#) R196.1
PCI_INT2: P7.A6(INTA#) R204.1
PCI_IRQ/INTA: JP1.B77
PCI_RST_OUT: P5.A15(RST#) P7.A15(RST#) R201.2 R202.2
PHY3.3VA: C89.2 JP1.B96 T3.2(TD-CT)
RS232_RXD0: P1.3 U3.13(R1IN)
RS232_RXD1: J20.1 U6.13(R1IN)
RS232_RXD2/RS232_CTS0: J20.4 R56.1 U3.8(R2IN)
RS232_RXD3/RS232_CTS1: J20.7 U6.8(R2IN)
RS232_TXD0: P1.2 U3.14(~{T1OUT})
RS232_TXD1: J20.2 U6.14(~{T1OUT})
RS232_TXD2/RS232_RTS0: J20.5 R57.1 U3.7(~{T2OUT})
RS232_TXD3/RS232_RTS1: J20.8 U6.7(~{T2OUT})
RTCP3.3V: J1.1 JP1.B105
SATA1_pRX+: C95.1 P8.6(B+)
SATA1_pRX-: C94.1 P8.5(B-)
SATA1_pTX+: C92.1 P8.2(A+)
SATA1_pTX-: C93.1 P8.3(A-)
SATA_RX0N: C94.2 JP1.B78
SATA_RX0P: C95.2 JP1.B79
SATA_TX0N: C93.2 JP1.B82
SATA_TX0P: C92.2 JP1.B81
UART_RXD0: JP1.B8 R52.1
UART_RXD1: JP1.B4 R48.1
UART_RXD2: JP1.B7 R53.1
UART_RXD3: JP1.B3 R49.1
UART_TXD0: JP1.B9 R50.2
UART_TXD1: JP1.B5 R54.2
UART_TXD2: JP1.B6 R51.2
UART_TXD3: JP1.B2 R55.2
UARTA_C1+: C36.2 U3.1(C1+)
UARTA_C1-: C36.1 U3.3(C1-)
UARTA_C2+: C37.2 U3.4(C2+)
UARTA_C2-: C37.1 U3.5(C2-)
UARTA_V+: C41.1 U3.2(V+)
UARTA_V-: C40.1 U3.6(V-)
UARTB_C1+: C42.2 U6.1(C1+)
UARTB_C1-: C42.1 U6.3(C1-)
UARTB_C2+: C43.2 U6.4(C2+)
UARTB_C2-: C43.1 U6.5(C2-)
UARTB_V+: C38.1 U6.2(V+)
UARTB_V-: C39.1 U6.6(V-)
USB1_BUS_N: JP1.B49 R60.1
USB1_BUS_P: JP1.B50 R61.1
USB1_CPEN: JP1.B48 U7.1(CTLA)
USB1_FAULT_N: JP1.B52 R59.1 U7.2(/FLGA)
USB1_P+: P10.3 R61.2
USB1_P-: P10.2 R60.2
USB1_PHY_ID: JP1.B53 R58.1
USB2_BUS_N: R256.1
USB2_BUS_P: R257.1
USB2_CPEN: R74.2 U7.4(CTLB)
USB2_P+: P10.7 R257.2
USB2_P-: P10.6 R256.2
user_IIC_SCL: P5.B10(Reserved2) P7.B10(Reserved2) R199.2
user_IIC_SDA: P5.A9(Reserved1) P7.A9(Reserved1) R200.2
user_LX0: R292.2 U31.38(D9)
user_LX1: R293.2 U31.42(D6)
user_LX2: R294.2 U31.43(D5)
user_LX3: R295.2 U31.44(D4)
user_LX4: R296.2 U31.45(D2)
user_OLX0: J21.34 R292.1
user_OLX4: J21.20 R296.1
N145290053: K6.3 K6.4 R7.1
N145305659: D4.A(ANODE) R25.2
N145305927: D5.A(ANODE) R26.2
N145306087: D6.A(ANODE) R27.2
N145306173: D7.A(ANODE) R28.2
N145306260: D9.A(ANODE) R29.2
N145315582: C30.1 K3.1 K3.2 R32.2 U4.3(/MR)
N145315928: K3.3 K3.4 R31.1
N145326060: R33.2 U4.2(/RESET)
N145339419: R39.2 R40.1 U13.7(WP)
N145339431: R41.2 U13.1(A0)
N145339441: R42.2 U13.2(A1)
N145339451: R43.2 U13.3(A2)
N145514935: P1.7 R56.2
N145515593: P1.8 R57.2
N145732025: FB1.1 P10.4 P10.8
N146157686: C79.2 R96.1 R97.1
N146157696: C76.1 R98.1 R99.1
N146157818: C81.2 T4.7(RD-)
N146178622: C82.2 R100.2 R105.2
N146178699: R100.1 R101.2 R102.2
N146178703: R103.2 R104.2 R105.1
N146190611: J6.12(A12) R107.1
N146190615: J6.10(A10) R106.1
N146196211: J4.12(A12) R109.1
N146196215: J4.10(A10) R108.1
N146203786: C88.2 R110.1 R111.1
N146203804: C85.1 R112.1 R113.1
N146203920: C90.2 T3.7(RD-)
N146228868: C91.2 R114.2 R119.2
N146228925: R114.1 R115.2 R116.2
N146228929: R117.2 R118.2 R119.1
N146689825: P5.A4(TDI) R187.2
N146689831: P5.A3(TMS) R186.2
N146689844: P5.A1(TRST#) R182.1
N146689857: P5.B9(PRSNT1#) R183.2
N146689869: P5.B2(TCK) R185.1
N146689882: P5.B11(PRSNT2#) R184.2
N147761377: C101.2 J3.2 L11.2
N147833646: C12.1 C104.2 C133.2 L8.2(B) L9.2(B) R225.2 U22.2(Vout) U22.4(Pad)
N147837857: R225.1 R226.1 U22.1(Adj)
N148313283: C112.2 P1.10 P1.11
N160047558: C121.1 L7.2(B) L10.2(B) U12.6(Vo)
N160047562: R249.1 U12.5(Vo_Adjust)
N160047588: R249.2 R250.1
N160047625: C118.1 L6.2(B) L12.2(B) U11.6(Vo)
N160047640: R248.1 U11.5(Vo_Adjust)
N160047858: R247.1 R248.2
N160048745: D0.K(CATHODE) R252.1
N160048747: D10.K(CATHODE) R253.1
N160048786: D11.K(CATHODE) R251.1
N160060162: C14.1 J2.4
N160087766: R50.1 U3.11(T1IN)
N160087768: R51.1 U3.10(T2IN)
N160087786: R52.2 U3.12(~{R1OUT})
N160087788: R53.2 U3.9(~{R2OUT})
N160088899: R48.2 U6.12(~{R1OUT})
N160088901: R49.2 U6.9(~{R2OUT})
N160088915: R54.1 U6.11(T1IN)
N160088917: R55.1 U6.10(T2IN)
N160089960: C47.1 R62.2 R63.2
N160090355: R64.1 U33.8(RS)
N160091354: C49.2 R71.2 R72.2 U33.5(/SHDN)
N160091739: C50.1 R65.2 R66.2
N160091787: R67.1 U36.8(RS)
N160091833: C52.2 R69.2 R70.2 U36.5(/SHDN)
N160094174: D12.A(ANODE) R30.2
N160094250: D13.A(ANODE) R34.2
N160107372: R270.2 U38.25(2/OE)
N160107484: R271.2 U39.25(2/OE)
N160110440: R272.2 R273.1 U39.1(1DIR)
N160113924: D14.A(ANODE) R254.2
N160115818: J21.1 R284.2
N160127131: J10.1 R17.2
N160127148: J10.15 R24.2
N160127451: J10.2 R16.1
N160127453: J10.4 R15.1
N160127455: J10.6 R14.1
N160127457: J10.8 R13.1
N160127459: J10.10 R12.1
N160127461: J10.12 R11.1
N160127463: J10.14 R10.1
N160127465: J10.16 R9.1
N160133554: R227.1 R228.1 U23.1(Adj)
N160169904: P7.A3(TMS) R198.2
N160169910: P7.A4(TDI) R197.2
N160169923: P7.A1(TRST#) R192.1
N160169930: P7.B2(TCK) R193.1
N160169942: P7.B9(PRSNT1#) R191.2
N160169946: P7.B11(PRSNT2#) R194.2
N160172557: JP1.B83 R289.2
N160177684: J7.6 R290.2
N160177687: J7.7 R291.2
N160179434: R133.2 U28.3(Q1)
N160179436: R120.2 U28.2(Q0)
N160187257: JP1.B54 Tr6.1(TP)
N160187294: JP1.B55 Tr8.1(TP)
N160189782: R297.2 U31.39(D8)
N160206297: R75.1 U7.3(/FLGB)

Not connected (* = marked no-connect by the designer): F0 1*; F1 1*; F2 1*; F3 1*; J1 3* 4*; J2 5; J4 15(HOL1)* 16(HOL2)*; J6 15(HOL1)* 16(HOL2)*; J12 3 4; J19 4*; JP1 M0* M1*; P1 1* 4* 6* 9*; P2 1* 4* 5 6* 8 9*; P5 A7(INTC#)* A11(Reserved3)* A19(PME#)* A40(SDONE)* A41(SBO#)* A60(REQ64#)* B4(TDO)* B7(INTB#)* B8(INTD#)* B14(Reserved4)* B39(LOCK#)* B60(ACK64#)*; P6 1* 4* 5 6* 8 9*; P7 A7(INTC#)* A11(Reserved3)* A19(PME#)* A40(SDONE)* A41(SBO#)* A60(REQ64#)* B4(TDO)* B7(INTB#)* B8(INTD#)* B14(Reserved4)* B39(LOCK#)* B60(ACK64#)*; T3 4* 5* 12* 13*; T4 4* 5* 12* 13*; U11 4(Inhibit); U12 4(Inhibit); U28 6(Q2) 7(Q3); U31 46(D1) 47(D0) 48(CLK1/I) 52(E0) 53(E1) 54(E2) 55(E4) 56(E5) 57(E6) 60(E8) 61(E9) 62(E10) 64(E14) 112(CLK3/I) 116(A0/GOE0); U39 17(2B4) 19(2B5) 20(2B6) 22(2B7) 23(2B8) 26(2A8) 27(2A7) 29(2A6) 30(2A5) 32(2A4)

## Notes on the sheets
sheet 1
- FPGA_user_IO/pci: 45pin
- PCI slot2
- PCI slot1
- project：
- designer：
- date：
- tile：
- page：
- www.greenbelltech.com
- PCI
- 歌林贝尔科技
sheet 2
- Section
- Title
- Page
- 1
- index
- 2
- BLOCK DIGRAM
- 3
- PCB LAYOUT
- 4
- SYS_INIT SCHEME
- GREEN
- TECH
- 5
- CORE_BUS_J1
- 6
- MPC_INIT
- 7
- SYS_CPLD
- 8
- MPC_LAN_PORT
- 9
- PORT_OUT
- DEMOTYPEA
- 10
- PCIA_USER_S
- 11
- USER_PORT_M
- 12
- POWER_IN
- GREEN  Logo
  for DEMOTYPEA core Board
- 13
- 14
- 15
- Board Rev. V1.00
- 16
- 17
- 18
- 19
- 20
- 成都歌林贝尔科技有限公司
- 歌林贝尔嵌入计算技术有限公司
- www.GreenBellTech.com
- V1.0
- 2016.09
- 1st
- GreenBell Embedded Technologies,Inc.
- REV：
- DATE：
- CHANGES：
- project：
- designer：
- date：
- tile：
- page：
- www.greenbelltech.com
- INDEX
- 歌林贝尔科技
sheet 3
- key_1-8
- cpld
- PLCC32
- LOCAL BUS
- DC+12V
- USB
- USB2.0
- CORE 模块
- 1588
- LAN1
- LAN1、2
- MODULE P1
- POWER
  DC-DC
- LAN2
- OTHER_BUS
- +3.3V/5.0V
- L
- USER_ADD_PORT
- +12V
- UART、I2C、SPI 、eSHDC、CAN
- RS232
- UART0
- SRIO or PCIE
  、SATA
- CAN1
- CAN
- PCI  BUS
- 2 x SATA
- CAN2
- CAN
- PCI_SLOT1
- RST
- KEY
- GPIO
- PCI_SLOT2
- LED
- project：
- designer：
- date：
- tile：
- page：
- www.greenbelltech.com
- BLOCK DIAGRAM
- 歌林贝尔科技
sheet 4
- RESET
- PWM_OUT0~15
- 16PWM输出
- LBC_CLK
- PWM_IN0~3
- 4路PWM捕获
- LBC_CS
- 扩展接口
- LBC_OE
- F_IN0
- 接处理器局部总线
- LBC_WE
- 2路频率量
- F_IN1
- LBC_ALE
- UART0~3
- 4路串口
- LBC_A/D0~31
- (或2路SPI,
  各含3个片选)
- LBC_IRQ0
- FPGA：XC6SLX16-CSG225
- project：
- designer：
- date：
- tile：
- page：
- www.greenbelltech.com
- PCB LAYOUT
- 歌林贝尔科技
sheet 5
- project：
- designer：
- date：
- tile：
- page：
- www.greenbelltech.com
- KITs SCHEME
- 歌林贝尔科技
sheet 6
- project：
- designer：
- date：
- tile：
- page：
- www.greenbelltech.com
- MPC_INIT
- 歌林贝尔科技
- checked 1107
sheet 7
- project：
- designer：
- date：
- tile：
- page：
- www.greenbelltech.com
- SYS_CPLD
- 歌林贝尔科技
sheet 8
- project：
- designer：
- date：
- tile：
- page：
- www.greenbelltech.com
- USER_PORT_M
- 歌林贝尔科技
sheet 9
- project：
- designer：
- date：
- tile：
- page：
- www.greenbelltech.com
- MPC LAN
- 歌林贝尔科技
sheet 10
- SATA
- UART
- CAN
- USB
- project：
- designer：
- date：
- tile：
- page：
- www.greenbelltech.com
- MPC_PER
- 歌林贝尔科技
sheet 11
- DC12V_Module_In
- ATX_Dc12V_In
- bak
- bak
- project：
- designer：
- date：
- tile：
- page：
- www.greenbelltech.com
- POWER
- 歌林贝尔科技
sheet 12
- USER BUS1
- project：
- designer：
- date：
- tile：
- page：
- www.greenbelltech.com
- CORE_BUS
- 歌林贝尔科技
